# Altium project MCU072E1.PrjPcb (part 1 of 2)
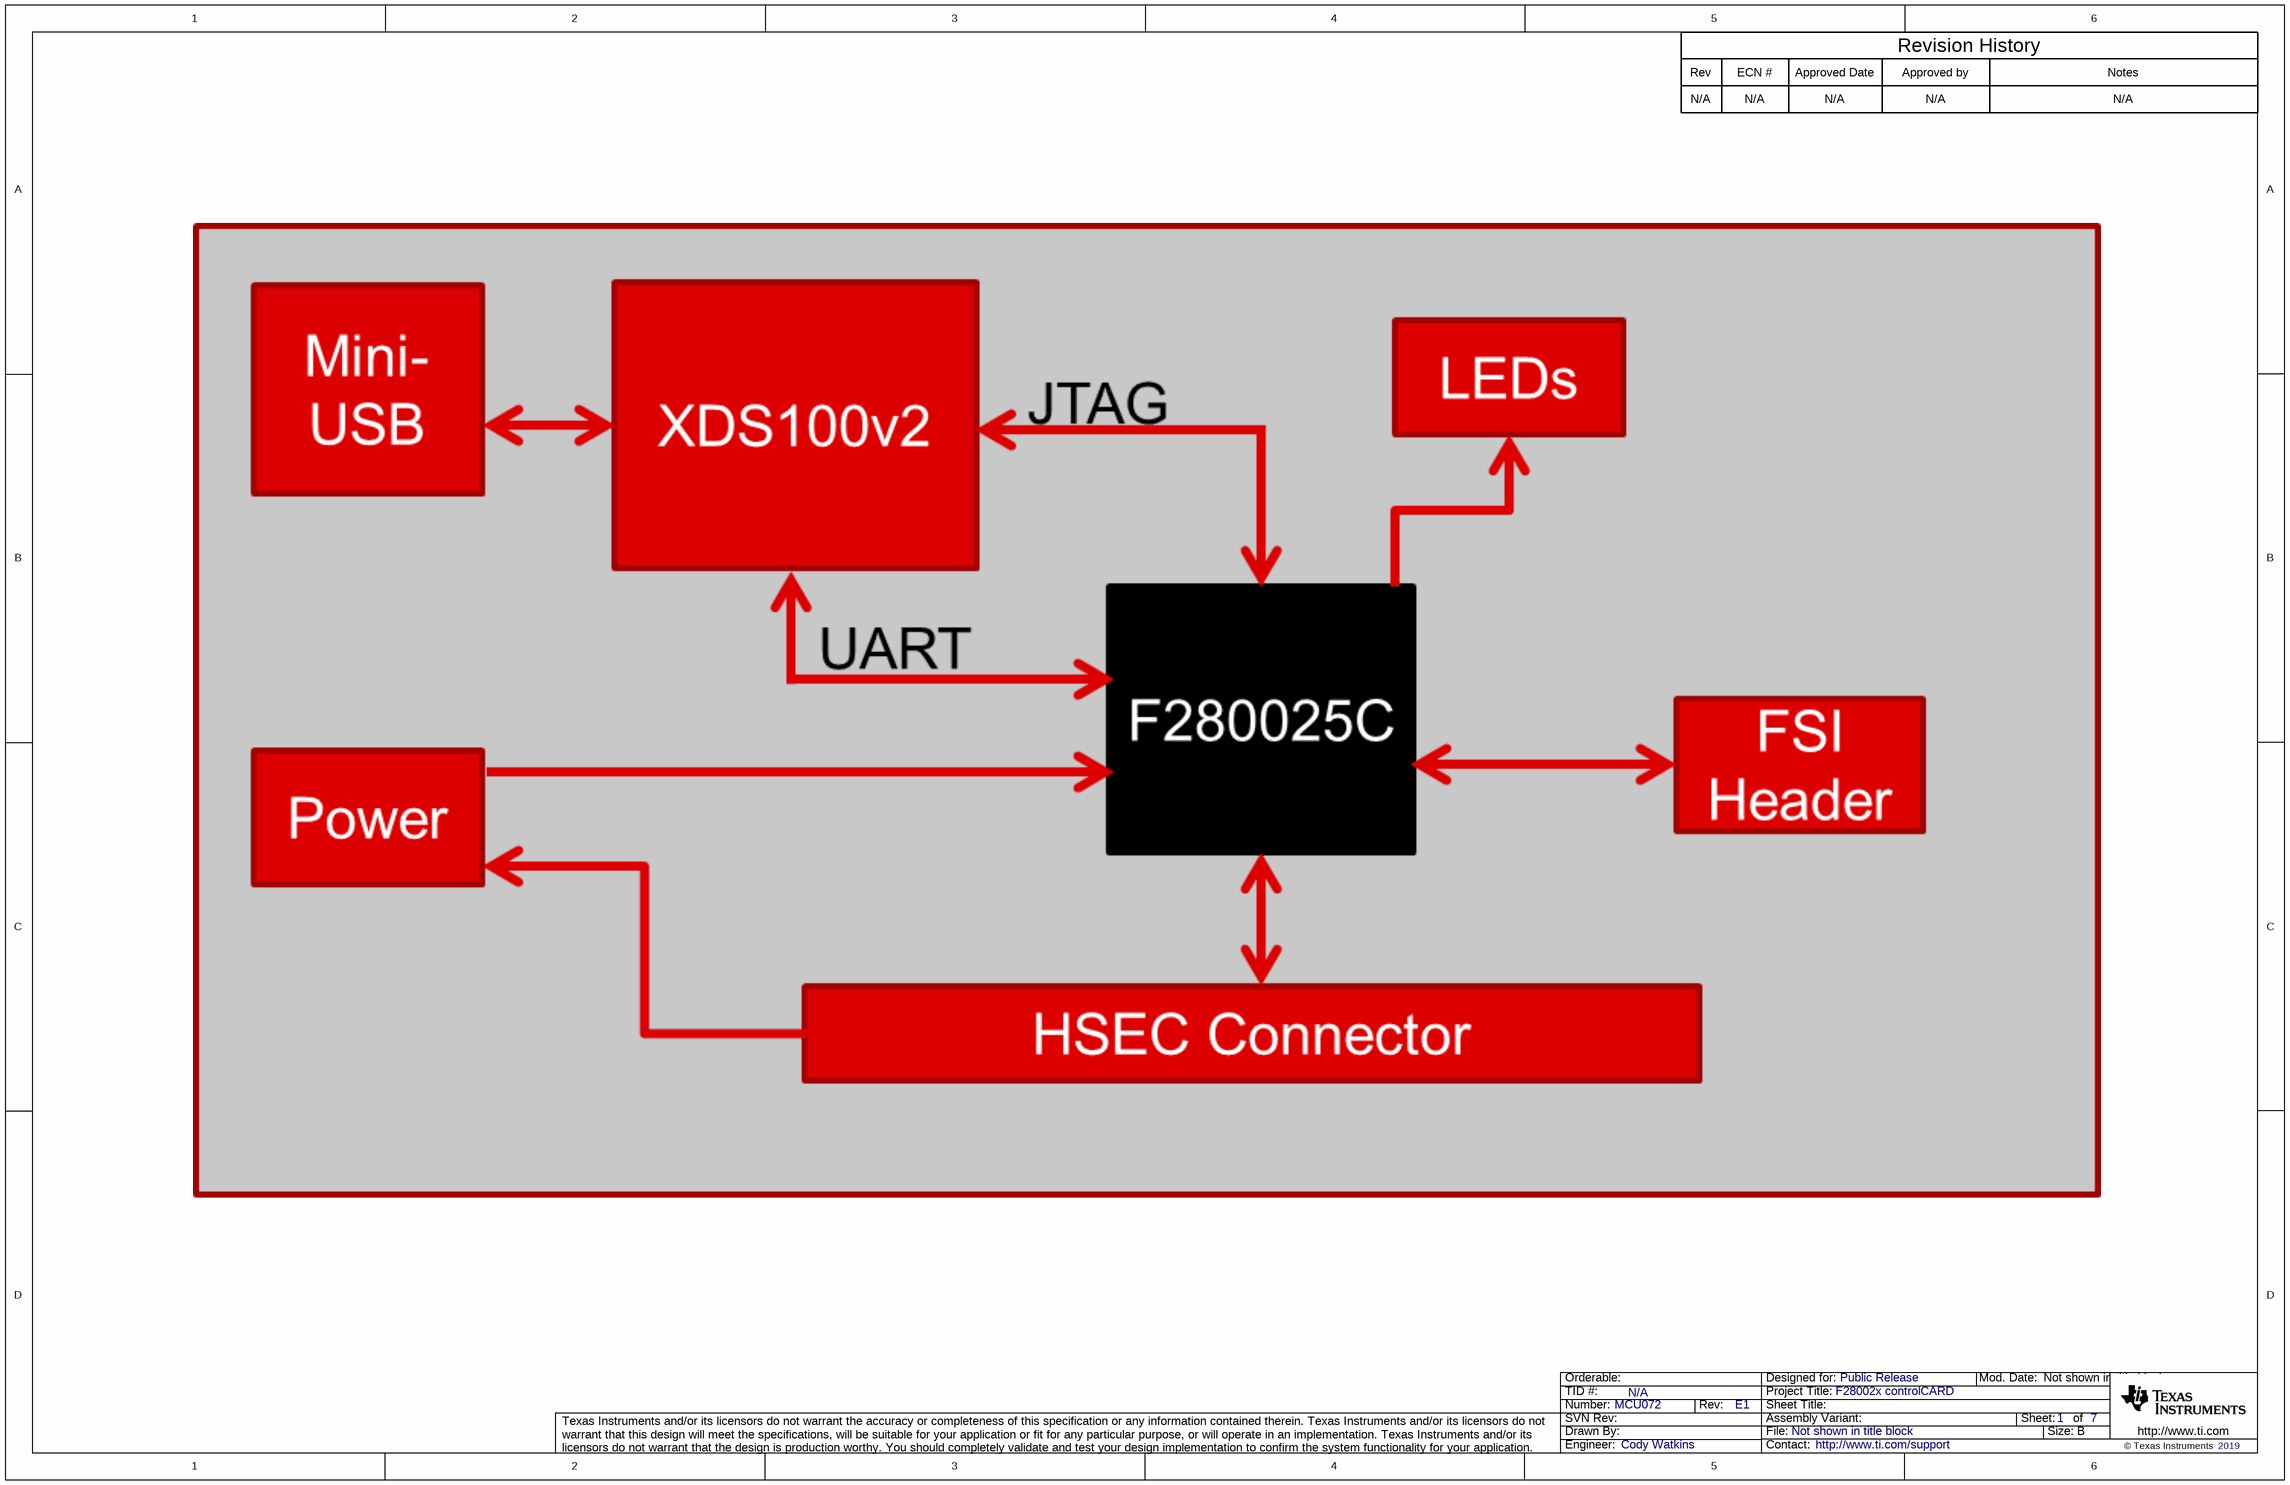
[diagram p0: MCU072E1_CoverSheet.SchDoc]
CopyrightYear: 2019; PCB_Layout: Cody Watkins; PCB_Rev: E1; PRJ_Customer: Public Release; PRJ_Engineer: Cody Watkins; PRJ_Number: MCU072; PRJ_Title: F28002x controlCARD; SCH_Rev: E1; TechSupport: http://www.ti.com/support; TID: N/A
7 sheets, 187 parts. Net scope: global (net labels, ports and power ports of the same name join across sheets).
Board file: MCU072E1_PCB.PcbDoc
Sheets:
  MCU072E1_CoverSheet.SchDoc
  MCU072E1_GPIO.SchDoc
  MCU072E1_Power.SchDoc
  MCU072E1_ADC.SchDoc
  MCU072E1_Emulator_Hardware.SchDoc
  MCU072E1_Emulator_Interface.SchDoc
  MCU072E1_Hardware.SchDoc

## Sheet MCU072E1_CoverSheet.SchDoc
size 431 x 279 mm; Date: Not shown in title block; ApprovedBy: Not shown in title block; CheckedBy: Not shown in title block; Author: Not shown in title block; CompanyName: Not shown in title block; Engineer: Not shown in title block; Organization: Not shown in title block; Address1: Not shown in title block; Address2: Not shown in title block; Address3: Not shown in title block; Address4: Not shown in title block; DocumentNumber: 1; Revision: Use project parameter SCH_Rev; SheetNumber: 1; SheetTotal: 7; PageSetup: Record=PageOptions¦CenterHorizontal=True¦CenterVertical=True¦PrintScale=1.00¦XCorrection=1.00¦YCorrection=1.00¦PrintKind=0¦BorderSize=5000000¦LeftOffset=0¦BottomOffset=0¦Orientation=2¦PaperLength=1000¦PaperWidth=1000¦Scale=100¦PaperSource=15¦PrintQuality=600¦MediaType=1¦DitherType=10¦PaperKind=Letter¦PrintScaleMode=1

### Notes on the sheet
- Rev
- N/A
- ECN #
- Approved Date
- Approved by
- Revision History
- Notes

## Sheet MCU072E1_GPIO.SchDoc
size 431 x 279 mm; Date: Not shown in title block; ApprovedBy: Not shown in title block; CheckedBy: Not shown in title block; Author: Not shown in title block; CompanyName: Not shown in title block; DrawnBy: Cody Watkins; Engineer: Not shown in title block; Organization: Not shown in title block; Address1: Not shown in title block; Address2: Not shown in title block; Address3: Not shown in title block; Address4: Not shown in title block; DocumentNumber: 2; Revision: Use project parameter SCH_Rev; SheetNumber: 2; SheetTotal: 7; PageSetup: Record=PageOptions¦CenterHorizontal=True¦CenterVertical=True¦PrintScale=1.00¦XCorrection=1.00¦YCorrection=1.00¦PrintKind=0¦BorderSize=5000000¦LeftOffset=0¦BottomOffset=0¦Orientation=2¦PaperLength=1000¦PaperWidth=1000¦Scale=100¦PaperSource=15¦PrintQuality=600¦MediaType=1¦DitherType=10¦PaperKind=Letter¦PrintScaleMode=1
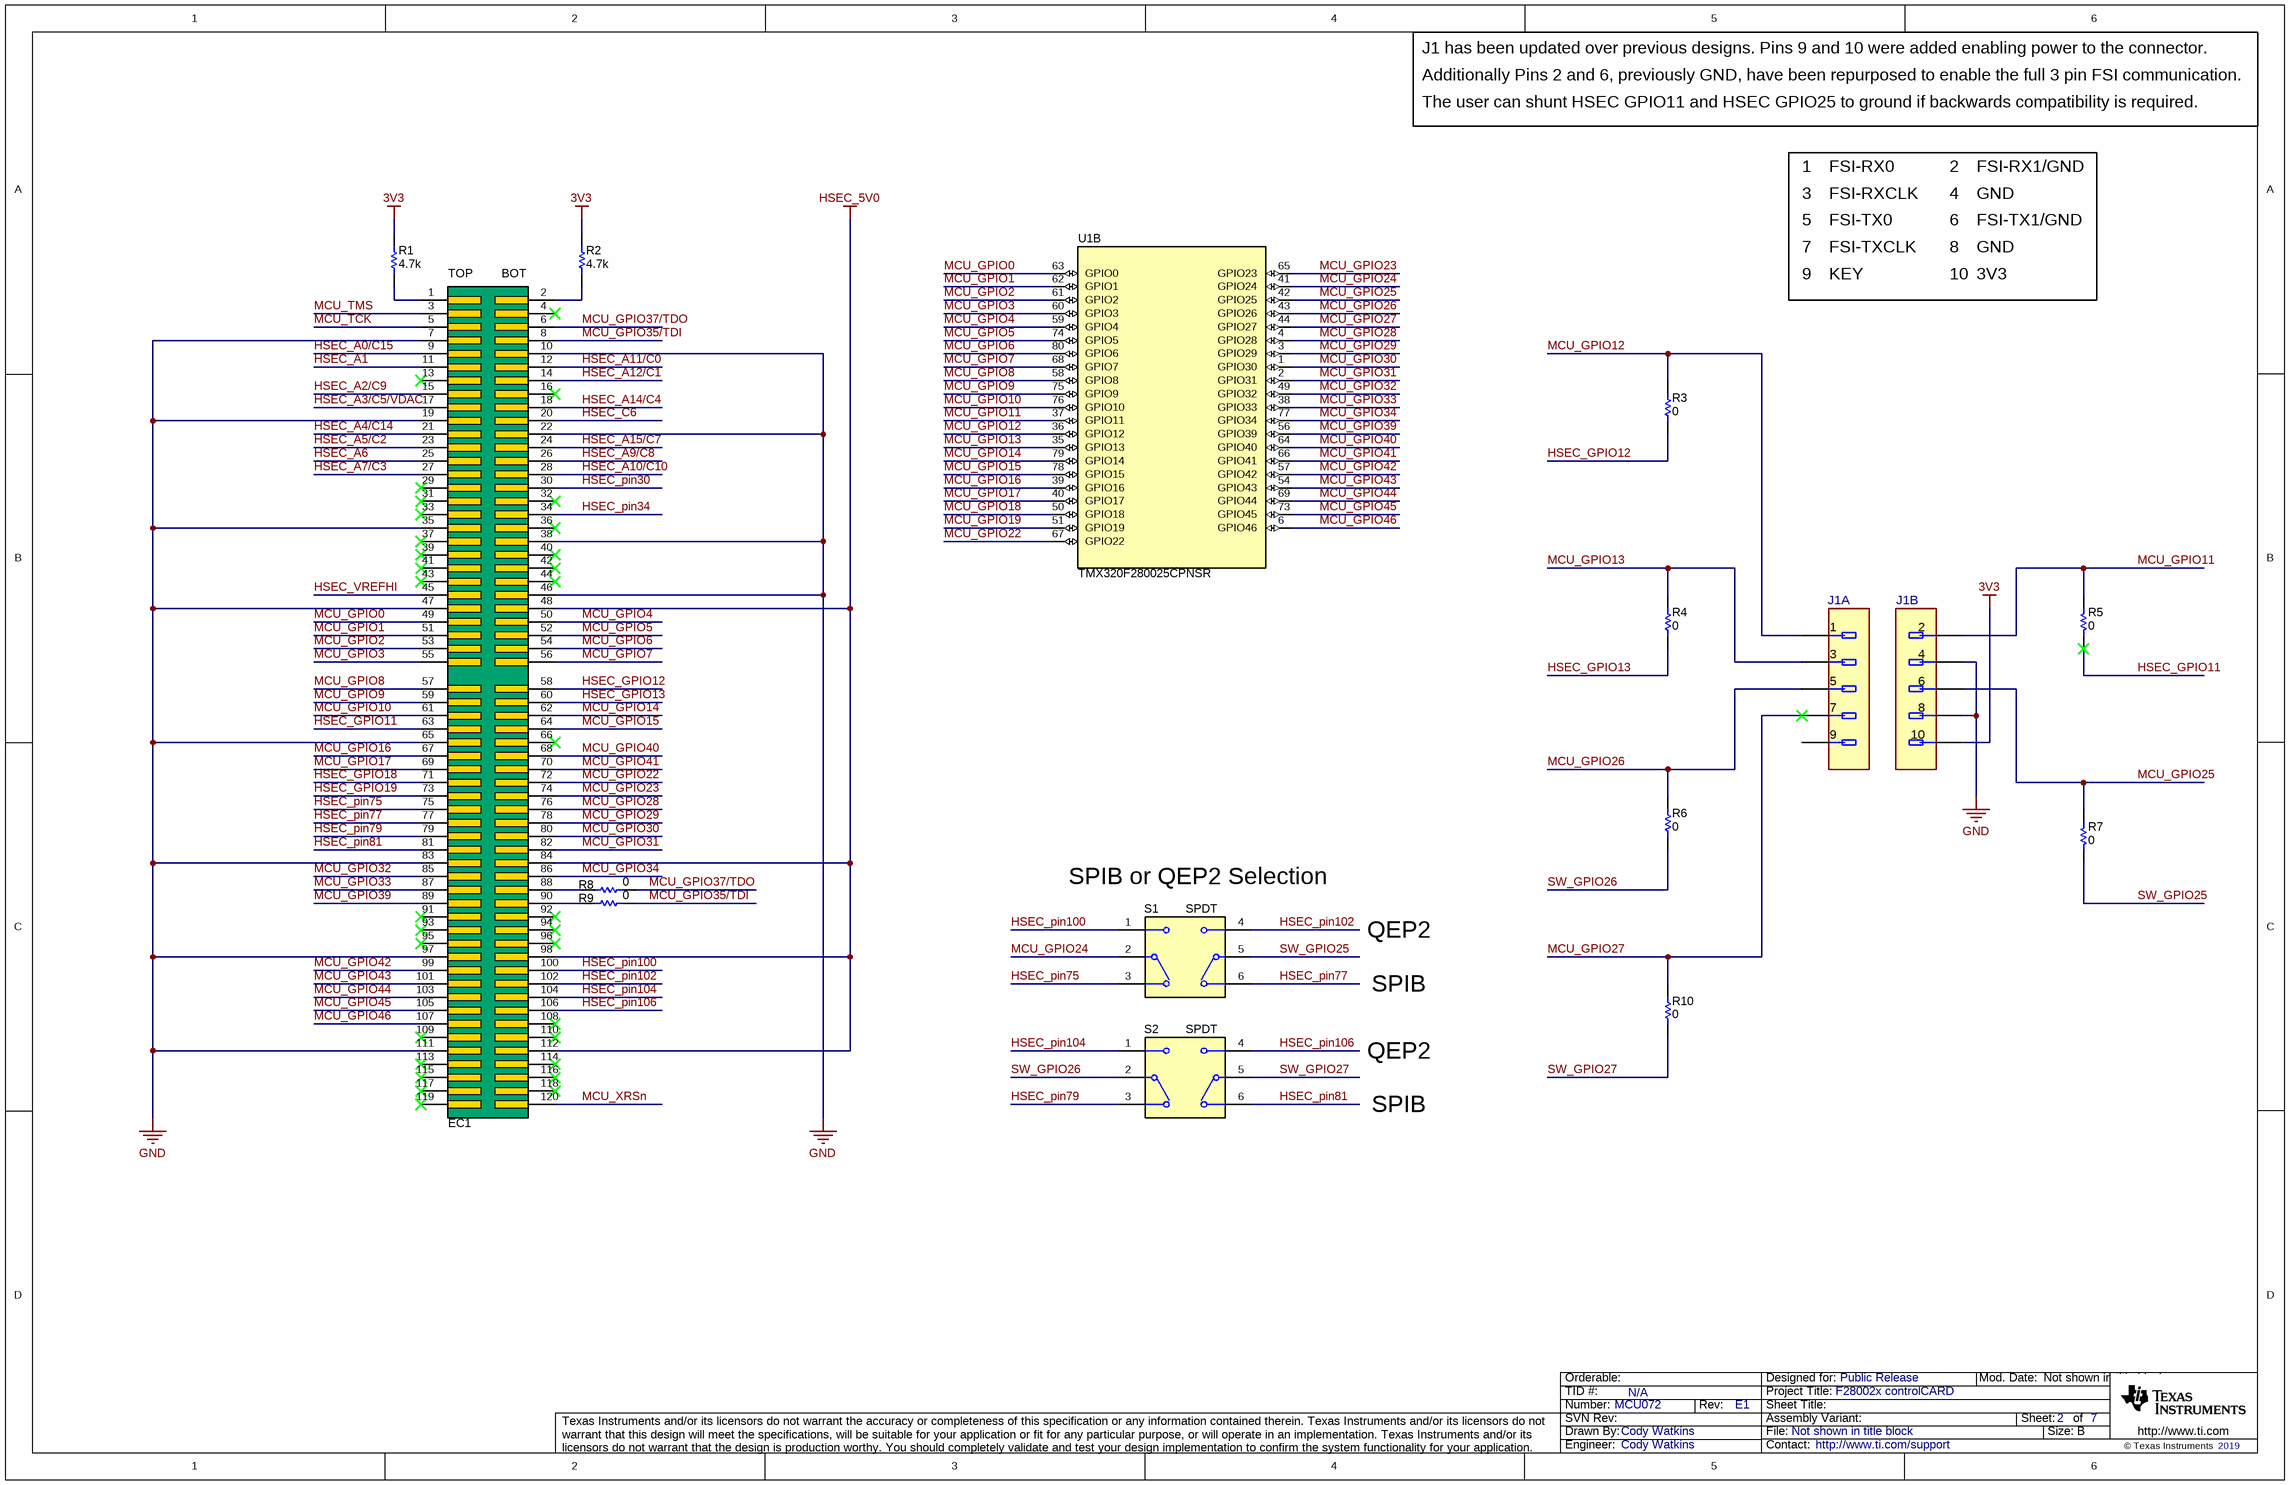
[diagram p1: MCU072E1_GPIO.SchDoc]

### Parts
EC1  controlCARD-120HSEC_Edge  [controlCARD-120HSEC_Edge]  (value not drawn)  (no BOM)
J1  TMM-105-01-T-D  [FP-TMM-105-01-T-D_HDR10-MFG]  (value not drawn)  (parts A,B of 2)
R1  ValueDisplayed: 4.7k  [0402]  (hidden comment: CRCW04024K70JNED)
R2  ValueDisplayed: 4.7k  [0402]  (hidden comment: CRCW04024K70JNED)
R3  ValueDisplayed: 0  [0603]  (hidden comment: CRCW06030000Z0EA)
R4  ValueDisplayed: 0  [0603]  (hidden comment: CRCW06030000Z0EA)
R5  ValueDisplayed: 0  [0603]  (hidden comment: CRCW06030000Z0EA)
R6  ValueDisplayed: 0  [0603]  (hidden comment: CRCW06030000Z0EA)
R7  ValueDisplayed: 0  [0603]  (hidden comment: CRCW06030000Z0EA)
R8  ValueDisplayed: 0  [0603]  (hidden comment: CRCW06030000Z0EA)
R9  ValueDisplayed: 0  [0603]  (hidden comment: CRCW06030000Z0EA)
R10  ValueDisplayed: 0  [0603]  (hidden comment: CRCW06030000Z0EA)
S1  Circuit: SPDT  [SW_CAS-D20TA]  (hidden comment: CAS-D20TA)
S2  Circuit: SPDT  [SW_CAS-D20TA]  (hidden comment: CAS-D20TA)
U1  TMX320F280025CPNSR  [PN0080A_N]  (part B of 4)

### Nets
3V3: J1.10 R1.1 R2.2
GND: EC1.7 EC1.10 EC1.19 EC1.22 EC1.35 EC1.38 EC1.46 EC1.47 EC1.65 EC1.83 EC1.97 EC1.111 J1.4 J1.8
HSEC_5V0: EC1.48 EC1.84 EC1.98 EC1.112
HSEC_A0/C15: EC1.9
HSEC_A1: EC1.11
HSEC_A2/C9: EC1.15
HSEC_A3/C5/VDAC: EC1.17
HSEC_A4/C14: EC1.21
HSEC_A5/C2: EC1.23
HSEC_A6: EC1.25
HSEC_A7/C3: EC1.27
HSEC_A9/C8: EC1.26
HSEC_A10/C10: EC1.28
HSEC_A11/C0: EC1.12
HSEC_A12/C1: EC1.14
HSEC_A14/C4: EC1.18
HSEC_A15/C7: EC1.24
HSEC_C6: EC1.20
HSEC_GPIO11: EC1.63 R5.1
HSEC_GPIO12: EC1.58 R3.1
HSEC_GPIO13: EC1.60 R4.1
HSEC_GPIO18: EC1.71
HSEC_GPIO19: EC1.73
HSEC_pin30: EC1.30
HSEC_pin34: EC1.34
HSEC_pin75: EC1.75 S1.3
HSEC_pin77: EC1.77 S1.6
HSEC_pin79: EC1.79 S2.3
HSEC_pin81: EC1.81 S2.6
HSEC_pin100: EC1.100 S1.1
HSEC_pin102: EC1.102 S1.4
HSEC_pin104: EC1.104 S2.1
HSEC_pin106: EC1.106 S2.4
HSEC_VREFHI: EC1.45
MCU_GPIO0: EC1.49 U1.63(GPIO0)
MCU_GPIO1: EC1.51 U1.62(GPIO1)
MCU_GPIO2: EC1.53 U1.61(GPIO2)
MCU_GPIO3: EC1.55 U1.60(GPIO3)
MCU_GPIO4: EC1.50 U1.59(GPIO4)
MCU_GPIO5: EC1.52 U1.74(GPIO5)
MCU_GPIO6: EC1.54 U1.80(GPIO6)
MCU_GPIO7: EC1.56 U1.68(GPIO7)
MCU_GPIO8: EC1.57 U1.58(GPIO8)
MCU_GPIO9: EC1.59 U1.75(GPIO9)
MCU_GPIO10: EC1.61 U1.76(GPIO10)
MCU_GPIO11: J1.2 R5.2 U1.37(GPIO11)
MCU_GPIO12: J1.1 R3.2 U1.36(GPIO12)
MCU_GPIO13: J1.3 R4.2 U1.35(GPIO13)
MCU_GPIO14: EC1.62 U1.79(GPIO14)
MCU_GPIO15: EC1.64 U1.78(GPIO15)
MCU_GPIO16: EC1.67 U1.39(GPIO16)
MCU_GPIO17: EC1.69 U1.40(GPIO17)
MCU_GPIO18: U1.50(GPIO18)
MCU_GPIO19: U1.51(GPIO19)
MCU_GPIO22: EC1.72 U1.67(GPIO22)
MCU_GPIO23: EC1.74 U1.65(GPIO23)
MCU_GPIO24: S1.2(C) U1.41(GPIO24)
MCU_GPIO25: J1.6 R7.2 U1.42(GPIO25)
MCU_GPIO26: J1.5 R6.2 U1.43(GPIO26)
MCU_GPIO27: J1.7 R10.2 U1.44(GPIO27)
MCU_GPIO28: EC1.76 U1.4(GPIO28)
MCU_GPIO29: EC1.78 U1.3(GPIO29)
MCU_GPIO30: EC1.80 U1.1(GPIO30)
MCU_GPIO31: EC1.82 U1.2(GPIO31)
MCU_GPIO32: EC1.85 U1.49(GPIO32)
MCU_GPIO33: EC1.87 U1.38(GPIO33)
MCU_GPIO34: EC1.86 U1.77(GPIO34)
MCU_GPIO35/TDI: EC1.8 R9.1
MCU_GPIO37/TDO: EC1.6 R8.1
MCU_GPIO39: EC1.89 U1.56(GPIO39)
MCU_GPIO40: EC1.68 U1.64(GPIO40)
MCU_GPIO41: EC1.70 U1.66(GPIO41)
MCU_GPIO42: EC1.99 U1.57(GPIO42)
MCU_GPIO43: EC1.101 U1.54(GPIO43)
MCU_GPIO44: EC1.103 U1.69(GPIO44)
MCU_GPIO45: EC1.105 U1.73(GPIO45)
MCU_GPIO46: EC1.107 U1.6(GPIO46)
MCU_TCK: EC1.5
MCU_TMS: EC1.3
MCU_XRSn: EC1.120
SW_GPIO25: R7.1 S1.5(C)
SW_GPIO26: R6.1 S2.2(C)
SW_GPIO27: R10.1 S2.5(C)
NetEC1_1: EC1.1 R1.2
NetEC1_2: EC1.2 R2.1
NetEC1_88: EC1.88 R8.2
NetEC1_90: EC1.90 R9.2

Not connected (* = marked no-connect by the designer): EC1 4* 13* 16* 29* 31* 32* 33* 36* 37* 39* 40* 41* 42* 43* 44* 66* 91* 92* 93* 94* 95* 96* 108* 109* 110* 113* 114* 115* 116* 117* 118* 119*; J1 9

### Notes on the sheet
- J1 has been updated over previous designs. Pins 9 and 10 were added enabling power to the connector.
- Additionally Pins 2 and 6, previously GND, have been repurposed to enable the full 3 pin FSI communication.
- The user can shunt HSEC GPIO11 and HSEC GPIO25 to ground if backwards compatibility is required.
- 1
- FSI-RX0
- 2
- FSI-RX1/GND
- 3
- 5
- FSI-RXCLK
- FSI-TX0
- 4
- 6
- FSI-TX1/GND
- GND
- 7
- 9
- FSI-TXCLK
- KEY
- 8
- 10
- 3V3
- (near S1) SPIB or QEP2 Selection
- QEP2
- SPIB

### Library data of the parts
EC1 = CMP-0003813-2: C2000 controlCARD-120HSEC Edge Connector for Samtec HSEC8-160-01-L-DV-A-BL; Manufacturer: Any; Note: The pin numbering does not match Samtec datasheet
J1 = CMP-0086568-1: Board-To-Board Connector, TMM Series, 10 Contacts, Header, 2 mm, Through Hole, 2 Rows; Manufacturer: Samtec; ContactFinish: Tin,Nickel; Voltage_V: 281V; Symbol Name: SYM-TMM-105-01-T-D; Row_Count: 2; Current_A: 3.2A
R1 R2 = CMP-0026938-5: RES, 4.7 k, 5%, 0.063 W, AEC-Q200 Grade 0, 0402; Manufacturer: Vishay-Dale; Value: 4.7k; Value_Code: 4k70; Power_W: 63mW; Value2: 0.063W; VDC_V: 50V; TempCo: 200 ppm/C; EIA_Code: E24; AEC Category: Q200; AEC Qualified: Y; AEC Grade: 0; SizeArea_mm2: 0.5; SizeX_mm: 1; SizeZ_mm: 0.6
R3-R10 = CMP-0025697-4: RES, 0, 5%, 0.1 W, AEC-Q200 Grade 0, 0603; Manufacturer: Vishay-Dale; Value: 0; Value_Code: 0000; Power_W: 100mW; Value2: 0.1W; VDC_V: 75V; TempCo: 200 ppm/C; EIA_Code: E24; AEC Category: Q200; AEC Qualified: Y; SizeArea_mm2: 1.28; SizeX_mm: 1.6; SizeY_mm: 0.8; SizeZ_mm: 1
S1 S2 = CMP-0002233-1: Switch, Dual SPDT,  2 Pos, 0.1A, 6VDC, SMD; Manufacturer: Copal Electronics; VDC_V: 6V; SwitchFunction: On-On; PositionCount: 2; CurrentRating_mA: 100A
U1 = CMP-0750188-2: TMX320F280025CPNSR, PN0080A (LQFP-80); Alternate Manufacturer: Texas Instruments; SizeY_mm: 14; CompType: IC; AEC Category: Q200; AEC Qualified: N; SizeAreaWB_mm2: 256; SizeArea_mm2: 196; SizeZ_mm: 1.6

## Sheet MCU072E1_Power.SchDoc
size 431 x 279 mm; Date: Not shown in title block; ApprovedBy: Not shown in title block; CheckedBy: Not shown in title block; Author: Not shown in title block; CompanyName: Not shown in title block; DrawnBy: Cody Watkins; Engineer: Not shown in title block; Organization: Not shown in title block; Address1: Not shown in title block; Address2: Not shown in title block; Address3: Not shown in title block; Address4: Not shown in title block; DocumentNumber: 3; Revision: Use project parameter SCH_Rev; SheetNumber: 3; SheetTotal: 7; PageSetup: Record=PageOptions¦CenterHorizontal=True¦CenterVertical=True¦PrintScale=1.00¦XCorrection=1.00¦YCorrection=1.00¦PrintKind=0¦BorderSize=5000000¦LeftOffset=0¦BottomOffset=0¦Orientation=2¦PaperLength=1000¦PaperWidth=1000¦Scale=100¦PaperSource=15¦PrintQuality=600¦MediaType=1¦DitherType=10¦PaperKind=Letter¦PrintScaleMode=1
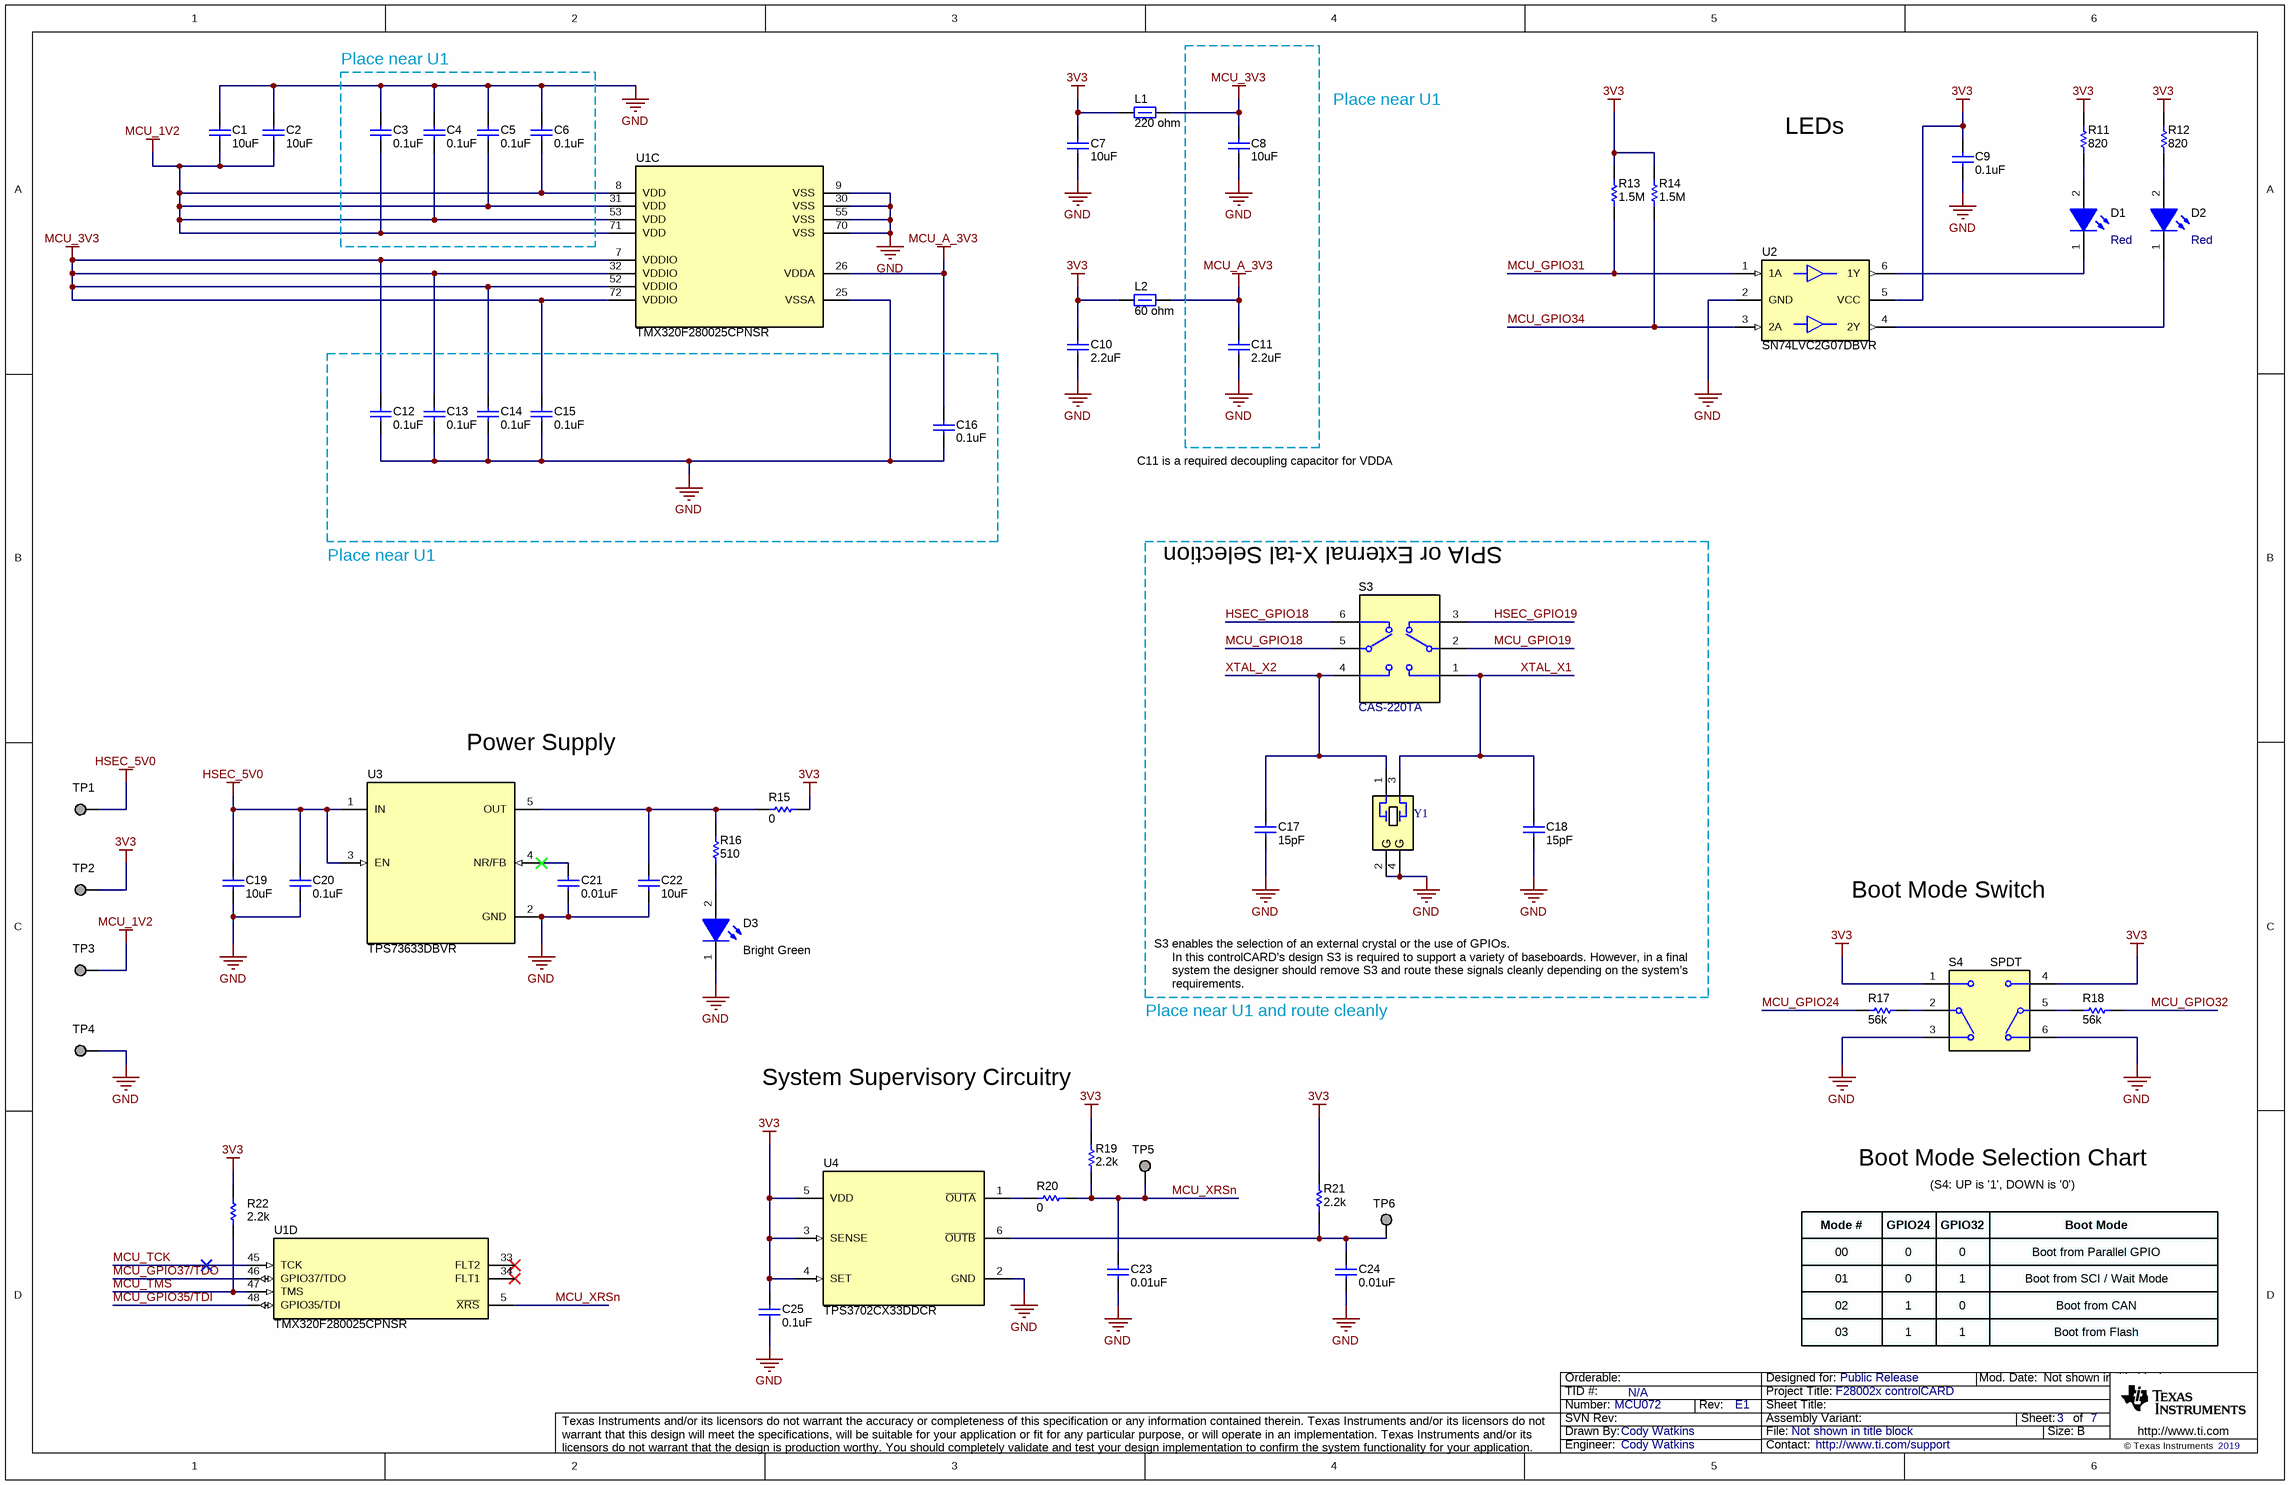
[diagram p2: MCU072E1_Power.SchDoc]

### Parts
C1  ValueDisplayed: 10uF  [0603]  (hidden comment: GRM188R61A106ME69D)
C2  ValueDisplayed: 10uF  [0603]  (hidden comment: GRM188R61A106ME69D)
C3  ValueDisplayed: 0.1uF  [0402]  (hidden comment: 885012105010)
C4  ValueDisplayed: 0.1uF  [0402]  (hidden comment: 885012105010)
C5  ValueDisplayed: 0.1uF  [0402]  (hidden comment: 885012105010)
C6  ValueDisplayed: 0.1uF  [0402]  (hidden comment: 885012105010)
C7  ValueDisplayed: 10uF  [0805_HV]  (hidden comment: LMK212ABJ106KG-T)
C8  ValueDisplayed: 10uF  [0603]  (hidden comment: GRM188R61A106ME69D)
C9  ValueDisplayed: 0.1uF  [0402]  (hidden comment: 885012105010)
C10  ValueDisplayed: 2.2uF  [0603]  (hidden comment: CGA3E3X5R1A225K080AB)
C11  ValueDisplayed: 2.2uF  [0603]  (hidden comment: CGA3E3X5R1A225K080AB)
C12  ValueDisplayed: 0.1uF  [0402]  (hidden comment: 885012105010)
C13  ValueDisplayed: 0.1uF  [0402]  (hidden comment: 885012105010)
C14  ValueDisplayed: 0.1uF  [0402]  (hidden comment: 885012105010)
C15  ValueDisplayed: 0.1uF  [0402]  (hidden comment: 885012105010)
C16  ValueDisplayed: 0.1uF  [0402]  (hidden comment: 885012105010)
C17  ValueDisplayed: 15pF  [0402]  (hidden comment: 885012005056)
C18  ValueDisplayed: 15pF  [0402]  (hidden comment: 885012005056)
C19  ValueDisplayed: 10uF  [0603]  (hidden comment: GRM188R61A106ME69D)
C20  ValueDisplayed: 0.1uF  [0402]  (hidden comment: 885012105010)
C21  ValueDisplayed: 0.01uF  [0402]  (hidden comment: 0402ZC103KAT2A)
C22  ValueDisplayed: 10uF  [0603]  (hidden comment: GRM188R61A106ME69D)
C23  ValueDisplayed: 0.01uF  [0402]  (hidden comment: 0402ZC103KAT2A)
C24  ValueDisplayed: 0.01uF  [0402]  (hidden comment: 0402ZC103KAT2A)
C25  ValueDisplayed: 0.1uF  [0402]  (hidden comment: 885012105010)
D1  value Red  [WL-SMCW_RED_0805]  (hidden comment: 150080SS75000)
D2  value Red  [WL-SMCW_RED_0805]  (hidden comment: 150080SS75000)
D3  value Bright Green  [WL-SMCW_Green_0805]  (hidden comment: 150080VS75000)
L1  value 220 ohm  [0805_HV]  (hidden comment: BLM21PG221SN1D)
L2  value 60 ohm  [0805_HV]  (hidden comment: BKP2125HS600-T)
R11  ValueDisplayed: 820  [0402]  (hidden comment: CRCW0402820RJNED)
R12  ValueDisplayed: 820  [0402]  (hidden comment: CRCW0402820RJNED)
R13  ValueDisplayed: 1.5M  [0402]  (hidden comment: CRCW04021M50JNED)
R14  ValueDisplayed: 1.5M  [0402]  (hidden comment: CRCW04021M50JNED)
R15  ValueDisplayed: 0  [0805_HV]  (hidden comment: CRCW08050000Z0EA)
R16  ValueDisplayed: 510  [0402]  (hidden comment: CRCW0402510RJNED)
R17  ValueDisplayed: 56k  [0402]  (hidden comment: CRCW040256K0JNED)
R18  ValueDisplayed: 56k  [0402]  (hidden comment: CRCW040256K0JNED)
R19  ValueDisplayed: 2.2k  [0402]  (hidden comment: CRCW04022K20JNED)
R20  ValueDisplayed: 0  [0402]  (hidden comment: CRCW04020000Z0ED)
R21  ValueDisplayed: 2.2k  [0402]  (hidden comment: CRCW04022K20JNED)
R22  ValueDisplayed: 2.2k  [0402]  (hidden comment: CRCW04022K20JNED)
S3  CAS-220TA  [SW_CAS-220TA]
S4  Circuit: SPDT  [SW_CAS-D20TA]  (hidden comment: CAS-D20TA)
TP1  TESTPOINT  [TP_50MIL-25MILHOLE]  (value not drawn)  (no BOM)
TP2  TESTPOINT  [TP_50MIL-25MILHOLE]  (value not drawn)  (no BOM)
TP3  TESTPOINT  [TP_50MIL-25MILHOLE]  (value not drawn)  (no BOM)
TP4  TESTPOINT  [TP_50MIL-25MILHOLE]  (value not drawn)  (no BOM)
TP5  TESTPOINT  [TP_50MIL-25MILHOLE]  (value not drawn)  (no BOM)
TP6  TESTPOINT  [TP_50MIL-25MILHOLE]  (value not drawn)  (no BOM)
U1  TMX320F280025CPNSR  [PN0080A_N]  (parts C,D of 4)
U2  SN74LVC2G07DBVR  [DBV0006A_N]
U3  TPS73633DBVR  [DBV0005A_N]
U4  TPS3702CX33DDCR  [DDC0006A_N]
Y1  ECS-200-18-30B-AGN-TR  [ECS_ECX-53B]  (value not drawn)

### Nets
3V3: C7.2 C9.1 C10.2 C25.1 L1.1 L2.1 R11.2 R12.2 R13.2 R14.2 R15.2 R19.2 R21.2 R22.2 S4.1 S4.4 TP2.1 U2.5(VCC) U4.3(SENSE) U4.4(SET) U4.5(VDD)
GND: C1.2 C2.2 C3.1 C4.1 C5.1 C6.1 C7.1 C8.2 C9.2 C10.1 C11.1 C12.2 C13.2 C14.2 C15.2 C16.2 C17.2 C18.2 C19.2 C20.2 C21.1 C22.1 C23.1 C24.1 C25.2 D3.1(K) S4.3 S4.6 TP4.1 U1.9(VSS) U1.25(VSSA) U1.30(VSS) U1.55(VSS) U1.70(VSS) U2.2(GND) U3.2(GND) U4.2(GND) Y1.2(GND) Y1.4(GND)
HSEC_5V0: C19.1 C20.1 TP1.1 U3.1(IN) U3.3(EN)
MCU_1V2: C1.1 C2.1 C3.2 C4.2 C5.2 C6.2 TP3.1 U1.8(VDD) U1.31(VDD) U1.53(VDD) U1.71(VDD)
MCU_3V3: C8.1 C12.1 C13.1 C14.1 C15.1 L1.2 U1.7(VDDIO) U1.32(VDDIO) U1.52(VDDIO) U1.72(VDDIO)
MCU_A_3V3: C11.2 C16.1 L2.2 U1.26(VDDA)
HSEC_GPIO18: S3.6
HSEC_GPIO19: S3.3
MCU_GPIO18: S3.5
MCU_GPIO19: S3.2
MCU_GPIO24: R17.2
MCU_GPIO31: R13.1 U2.1(1A)
MCU_GPIO32: R18.1
MCU_GPIO34: R14.1 U2.3(2A)
MCU_GPIO35/TDI: U1.48(GPIO35/TDI)
MCU_GPIO37/TDO: U1.46(GPIO37/TDO)
MCU_TCK: U1.45(TCK)
MCU_TMS: R22.1 U1.47(TMS)
MCU_XRSn: C23.2 R19.1 R20.2 TP5.1 U1.5(~{XRS})
XTAL_X1: C18.1 S3.1 Y1.3
XTAL_X2: C17.1 S3.4 Y1.1
NetC21_2: C21.2 U3.4(NR/FB)
NetC22_2: C22.2 R15.1 R16.2 U3.5(OUT)
NetC24_2: C24.2 R21.1 TP6.1 U4.6(~{OUTB})
NetD1_1: D1.1(K) U2.6(1Y)
NetD1_2: D1.2(A) R11.1
NetD2_1: D2.1(K) U2.4(2Y)
NetD2_2: D2.2(A) R12.1
NetD3_2: D3.2(A) R16.1
NetR17_1: R17.1 S4.2(C)
NetR18_2: R18.2 S4.5(C)
NetR20_1: R20.1 U4.1(~{OUTA})

Not connected (* = marked no-connect by the designer): U1 33(FLT2)* 34(FLT1)*

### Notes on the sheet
- Place near U1
- LEDs
- C11 is a required decoupling capacitor for VDDA
- SPIA or External X-tal Selection
- Power Supply
- Boot Mode Switch
- In this controlCARD’s design S3 is required to support a variety of baseboards. However, in a final
- system the designer should remove S3 and route these signals cleanly depending on the system’s
- S3 enables the selection of an external crystal or the use of GPIOs.
- Place near U1 and route cleanly
- requirements.
- System Supervisory Circuitry
- Boot Mode Selection Chart
- Mode #
- GPIO24
- GPIO32
- (S4: UP is '1', DOWN is '0')
- Boot Mode
- 00
- 01
- 02
- 0
- 1
- Boot from Parallel GPIO
- Boot from SCI / Wait Mode
- Boot from CAN
- 03
- Boot from Flash

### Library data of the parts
C1 C2 C8 C19 C22 = CMP-0007318-5: CAP, CERM, 10 uF, 10 V, +/- 20%, X5R, 0603; Manufacturer: MuRata; Polarized: N; Value: 10uF; U/M: EA; Cap_F: 10µF; Value1: Unknown; VDC_V: 10V; TaMin_C: -55°C; TaMax_C: 85°C; AEC Category: Q200; SizeArea_mm2: 1.28; SizeAreaWB_mm2: 4.68; SizeX_mm: 1.6; SizeY_mm: 0.8; SizeZ_mm: 1
C3-C6 C12-C16 = CMP-0006221-2: CAP, CERM, 0.1 uF, 10 V, +/- 20%, X5R, 0402; Manufacturer: Wurth Elektronik; Polarized: N; Value: 0.1uF; U/M: EA; Cap_F: 100nF; Value1: Unknown; VDC_V: 10V; TaMin_C: -55°C; TaMax_C: 85°C; SizeArea_mm2: 0.5; SizeAreaWB_mm2: 3; SizeX_mm: 1; SizeZ_mm: 0.6; AEC Category: Q200
C7 = CMP-0008395-2: CAP, CERM, 10 uF, 10 V, +/- 10%, X5R, 0805; Manufacturer: Taiyo Yuden; Polarized: N; Value: 10uF; U/M: EA; Cap_F: 10µF; Value1: Unknown; VDC_V: 10V; TaMin_C: -55°C; TaMax_C: 85°C; Cap_Case: 0805; AEC Category: Q200; SizeArea_mm2: 2.5; SizeAreaWB_mm2: 6.75; SizeX_mm: 2; SizeY_mm: 1.25; SizeZ_mm: 1.45
C9 C20 C25 = CMP-0006221-2: CAP, CERM, 0.1 uF, 10 V, +/- 20%, X5R, 0402; Manufacturer: Wurth Elektronik; Polarized: N; Value: 0.1uF; U/M: EA; Cap_F: 100nF; Value1: Unknown; VDC_V: 10V; TaMin_C: -55°C; TaMax_C: 85°C; AEC Category: Q200; SizeArea_mm2: 0.5; SizeAreaWB_mm2: 3; SizeX_mm: 1; SizeZ_mm: 0.6
C10 C11 = CMP-0007091-5: CAP, CERM, 2.2 uF, 10 V, +/- 10%, X5R, AEC-Q200 Grade 3, 0603; Manufacturer: TDK; Polarized: N; Value: 2.2uF; U/M: EA; Cap_F: 2.2µF; Value1: Unknown; VDC_V: 10V; TaMin_C: -55°C; TaMax_C: 85°C; AEC Category: Q200; AEC Qualified: Y; AEC Grade: 3; SizeArea_mm2: 1.28; SizeAreaWB_mm2: 4.68; SizeX_mm: 1.6; SizeY_mm: 0.8; SizeZ_mm: 1
C17 C18 = CMP-0006216-2: CAP, CERM, 15 pF, 50 V, +/- 5%, C0G/NP0, 0402; Manufacturer: Wurth Elektronik; Polarized: N; Value: 15pF; U/M: EA; Value1: Unknown; VDC_V: 50V; TaMin_C: -55°C; TaMax_C: 125°C; AEC Category: Q200; SizeArea_mm2: 0.5; SizeAreaWB_mm2: 3; SizeX_mm: 1; SizeZ_mm: 0.6
C21 C23 C24 = CMP-0006203-2: CAP, CERM, 0.01 uF, 10 V, +/- 10%, X7R, 0402; Manufacturer: AVX; Polarized: N; Value: 0.01uF; U/M: EA; Cap_F: 10nF; Value1: Unknown; VDC_V: 10V; TaMin_C: -55°C; TaMax_C: 125°C; AEC Category: Q200; SizeArea_mm2: 0.5; SizeAreaWB_mm2: 3; SizeX_mm: 1; SizeZ_mm: 0.6
D1 D2 = CMP-0002951-3: LED, Red, SMD; Manufacturer: Wurth Elektronik; Type: AlInGaP; Vf_V: 1.9V; Io_A: 30mA; Vr_V: 5V; Ir_A: 25µA; Tjmax_C: 85°C; Power_TotalModule: 72mW; Value1: 0.072W; Angle: 140
D3 = CMP-0002960-2: LED, Bright Green, SMD; Manufacturer: Wurth Elektronik; Type: AlInGaP; Vf_V: 2V; Io_A: 20mA; Vr_V: 5V; Tjmax_C: 85°C; Power_TotalModule: 72mW; Value1: 0.072W; Angle: 140; U/M: EA
L1 = CMP-0003363-1: Ferrite Bead, 220 ohm @ 100 MHz, 2 A, 0805; Manufacturer: MuRata; Imax_A: 2A; DCR_ohm: 0.045; Value1: 0.045 ohm; ZTyp@100MHz_Ohm: 220; SizeArea_mm2: 2.5; SizeAreaWB_mm2: 6.75; SizeX_mm: 2; SizeY_mm: 1.25; SizeZ_mm: 1.45
L2 = CMP-0003306-1: Ferrite Bead, 60 ohm @ 100 MHz, 3 A, 0805; Manufacturer: Taiyo Yuden; Imax_A: 3A; DCR_ohm: 0.025; Value1: 0.025 ohm; ZTyp@100MHz_Ohm: 60; SizeArea_mm2: 2.5; SizeAreaWB_mm2: 6.75; SizeX_mm: 2; SizeY_mm: 1.25; SizeZ_mm: 1.45
R11 R12 = CMP-0026979-3: RES, 820, 5%, 0.063 W, AEC-Q200 Grade 0, 0402; Manufacturer: Vishay-Dale; Power_W: 63mW; TempCo: 200 ppm/C; Value_Code: 820R; Value: 820; EIA_Code: E24; SizeX_mm: 1; SizeY_mm: 0.5; SizeZ_mm: 0.6; Value2: 0.063W; AEC Qualified: Y; VDC_V: 50V; AEC Category: Q200; AEC Grade: 0
R13 R14 = CMP-0026863-2: RES, 1.5 M, 5%, 0.063 W, AEC-Q200 Grade 0, 0402; Manufacturer: Vishay-Dale; Power_W: 63mW; TempCo: 200 ppm/C; Value_Code: 1M50; Value: 1.5Meg; EIA_Code: E24; SizeX_mm: 1; SizeY_mm: 0.5; SizeZ_mm: 0.6; Value2: 0.063W; AEC Qualified: Y; VDC_V: 50V; AEC Category: Q200; AEC Grade: 0
R15 = CMP-0020442-3: RES, 0, 5%, 0.125 W, AEC-Q200 Grade 0, 0805; Manufacturer: Vishay-Dale; Value: 0; Value_Code: 0000; Power_W: 125mW; Value2: 0.125W; VDC_V: 150V; TempCo: 200 ppm/C; EIA_Code: E24; AEC Category: Q200; AEC Qualified: Y; SizeArea_mm2: 2.5; SizeX_mm: 2; SizeY_mm: 1.25; SizeZ_mm: 1.45
R16 = CMP-0026944-3: RES, 510, 5%, 0.063 W, AEC-Q200 Grade 0, 0402; Manufacturer: Vishay-Dale; Power_W: 63mW; TempCo: 200 ppm/C; Value_Code: 510R; Value: 510; EIA_Code: E24; SizeX_mm: 1; SizeY_mm: 0.5; SizeZ_mm: 0.6; Value2: 0.063W; AEC Qualified: Y; VDC_V: 50V; AEC Category: Q200; AEC Grade: 0
R17 R18 = CMP-0026949-3: RES, 56 k, 5%, 0.063 W, AEC-Q200 Grade 0, 0402; Manufacturer: Vishay-Dale; Value: 56k; Value_Code: 56k0; Power_W: 63mW; Value2: 0.063W; VDC_V: 50V; TempCo: 200 ppm/C; EIA_Code: E24; AEC Category: Q200; AEC Qualified: Y; AEC Grade: 0; SizeArea_mm2: 0.5; SizeX_mm: 1; SizeZ_mm: 0.6
R19 R21 R22 = CMP-0026890-5: RES, 2.2 k, 5%, 0.063 W, AEC-Q200 Grade 0, 0402; Manufacturer: Vishay-Dale; Value: 2.2k; Value_Code: 2k20; Power_W: 63mW; Value2: 0.063W; VDC_V: 50V; TempCo: 200 ppm/C; EIA_Code: E24; AEC Category: Q200; AEC Qualified: Y; AEC Grade: 0; SizeArea_mm2: 0.5; SizeX_mm: 1; SizeZ_mm: 0.6
R20 = CMP-0026822-3: RES, 0, 5%, 0.063 W, AEC-Q200 Grade 0, 0402; Manufacturer: Vishay-Dale; Value: 0; Value_Code: 0000; Power_W: 63mW; Value2: 0.063W; VDC_V: 50V; TempCo: 200 ppm/C; SizeArea_mm2: 0.5; SizeX_mm: 1; SizeZ_mm: 0.6; EIA_Code: E24; AEC Category: Q200; AEC Qualified: Y
S3 = CMP-0002123-2: SLIDE SWITCH DPDT  .1A, SMT; Manufacturer: Copal Electronics; CurrentRating_mA: 100A; SwitchFunction: On-On; VDC_V: 6V; PositionCount: 2
S4 = CMP-0002233-1: as S1 on sheet MCU072E1_GPIO
TP1-TP6 = CMP-0078143-2: TEST POINT.  No entry in BOM.
U1 = CMP-0750188-2: as U1 on sheet MCU072E1_GPIO
U2 = CMP-0051789-2: Dual Buffer/Driver with Open-Drain Output, DBV0006A, LARGE T&R; Manufacturer: Texas Instruments; 3-State Output: No; Bits(#): 2; F @ Nom Voltage(Max)(Mhz): 150; ICC @ Nom Voltage(Max)(mA): 0.01; Input Type: CMOS/TTL; Logic: True; Output Drive (IOL/IOH)(Max)(mA): 32/-32; Output Type: CMOS; Rating: Catalog; Sub-Family: Inverting Buffer/Driver; Technology Family: LVC; tpd @ Nom Voltage(Max)(ns): 8.6,4.4,3.7,2.9; VCC(Max)(V): 5.5; VCC(Min)(V): 1.65; Voltage(Nom)(V): 1.8,2.5,3.3,5; AEC Category: Q200; AEC Qualified: N; CompType: IC; Green_Lifecycle: Active; Green_REACh: Passed; SizeArea_mm2: 8.12; SizeAreaWB_mm2: 14.82; SizeX_mm: 2.8; SizeY_mm: 2.9; SizeZ_mm: 1.45
U3 = CMP-0036866-2: Single Output Low Noise LDO, 400 mA, Fixed 3.3 V Output, 1.7 to 5.5 V Input, with Reverse Current Protection, 5-pin SOT-23 (DBV), -40 to 85 degC, Green (RoHS & no Sb/Br); Manufacturer: Texas Instruments; Alternate PartNumber: TPS73633DBVT; Accuracy(%): 1; Fixed Output Options(V): 3.3; Iout(Max)(A): 0.4; Iq(Typ)(mA): 0.3; Rating: Catalog; SubFamily: Single Channel LDO; Vdo(Typ)(mV): 75; Vin(Max)(V): 5.5; Vin(Min)(V): 1.7; AEC Category: Q200; AEC Qualified: N; CompType: IC; Green_Lifecycle: Active; Green_REACh: Passed; SizeArea_mm2: 8.12; SizeAreaWB_mm2: 14.82; SizeX_mm: 2.8; SizeY_mm: 2.9; SizeZ_mm: 1.45
U4 = CMP-0067340-3: High-Accuracy, Fixed-Threshold OV/UV Monitor, DDC0006A (SOT-23-T-6); Alternate PartNumber: TPS3702CX33DDCT; Manufacturer: Texas Instruments; SizeZ_mm: 0.87; SizeX_mm: 1.65; SizeY_mm: 2.95; SizeArea_mm2: 4.8675; CompType: IC; SizeAreaWB_mm2: 10.4675; AEC Category: Q200
Y1 = CMP-0080365-2: Crystal, 20 MHz, 25 ppm, 18 pF, SMD; Manufacturer: ECS Inc.; Frequency Stability: 30 ppm; AEC Qualified: N; Frequency Tolerance: 25 ppm; AEC Category: Q200; TaMax_C: 85°C; Frequency_Fixed: 20MHz; TaMin_C: -40°C; Load Capacitance: 18 pF

## Sheet MCU072E1_ADC.SchDoc
size 431 x 279 mm; Date: Not shown in title block; ApprovedBy: Not shown in title block; CheckedBy: Not shown in title block; Author: Not shown in title block; CompanyName: Not shown in title block; DrawnBy: Cody Watkins; Engineer: Not shown in title block; Organization: Not shown in title block; Address1: Not shown in title block; Address2: Not shown in title block; Address3: Not shown in title block; Address4: Not shown in title block; DocumentNumber: 4; Revision: Use project parameter SCH_Rev; SheetNumber: 4; SheetTotal: 7; PageSetup: Record=PageOptions¦CenterHorizontal=True¦CenterVertical=True¦PrintScale=1.00¦XCorrection=1.00¦YCorrection=1.00¦PrintKind=0¦BorderSize=5000000¦LeftOffset=0¦BottomOffset=0¦Orientation=2¦PaperLength=1000¦PaperWidth=1000¦Scale=100¦PaperSource=15¦PrintQuality=600¦MediaType=1¦DitherType=10¦PaperKind=Letter¦PrintScaleMode=1
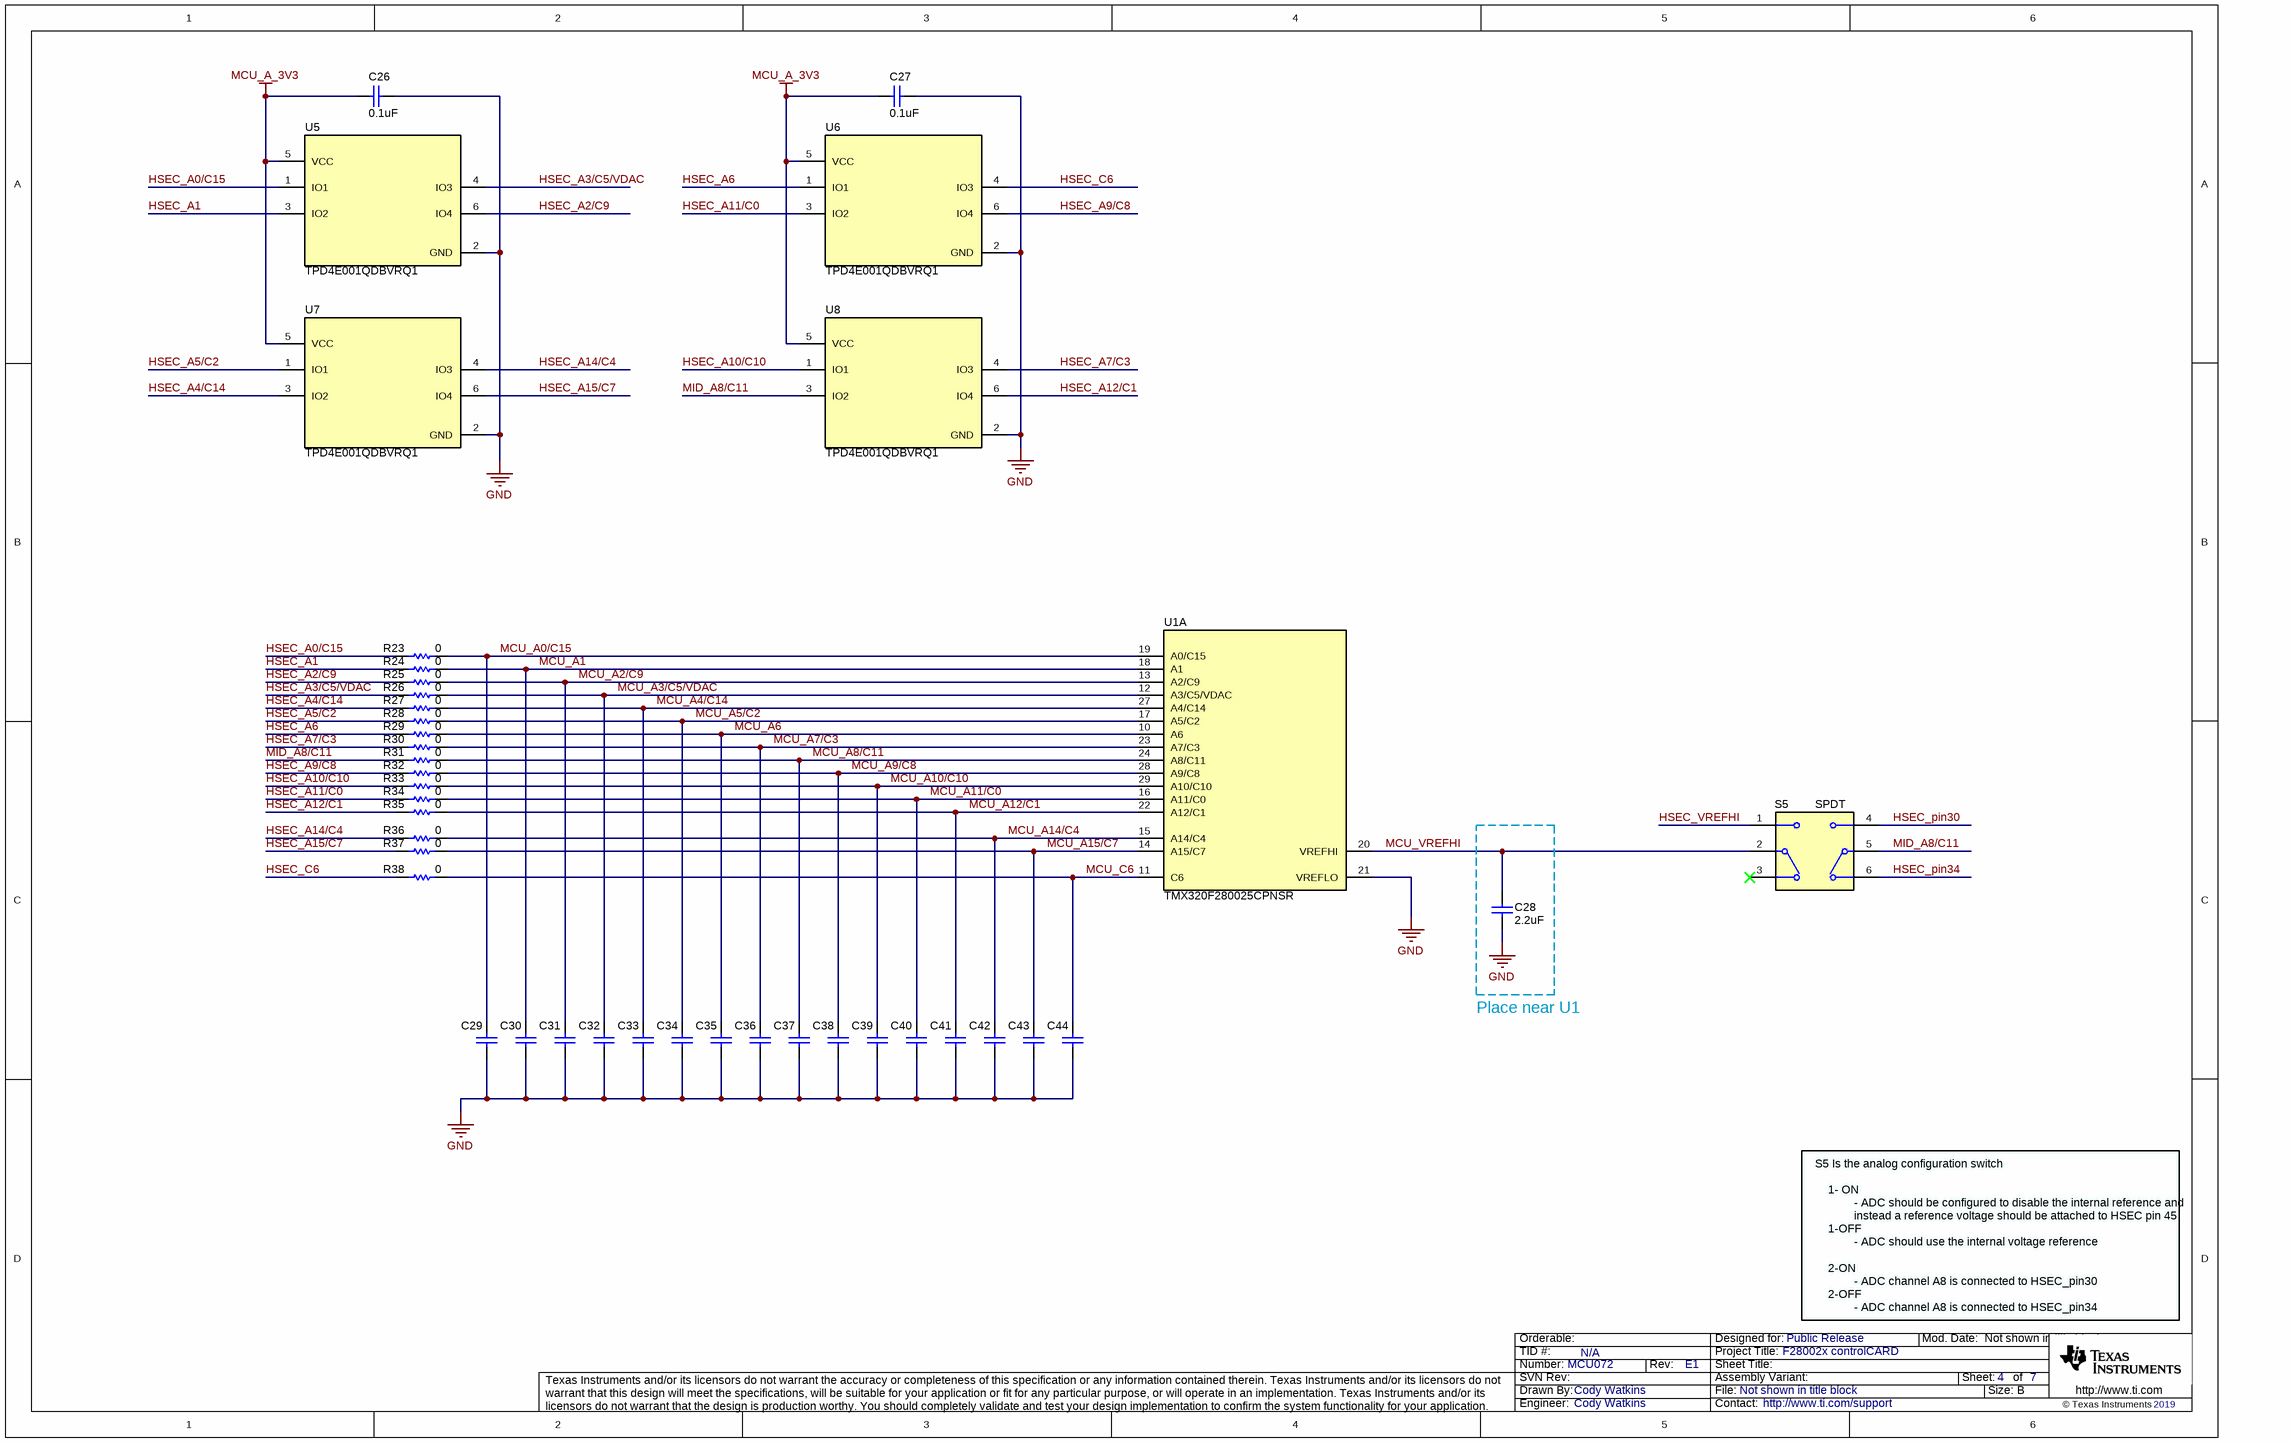
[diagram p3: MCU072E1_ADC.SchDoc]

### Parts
C26  ValueDisplayed: 0.1uF  [0402]  (hidden comment: 885012105010)
C27  ValueDisplayed: 0.1uF  [0402]  (hidden comment: 885012105010)
C28  ValueDisplayed: 2.2uF  [0603]  (hidden comment: CGA3E3X5R1A225K080AB)
C29  GRM188R71C104KA01D  [0603]  (value not drawn)
C30  GRM188R71C104KA01D  [0603]  (value not drawn)
C31  GRM188R71C104KA01D  [0603]  (value not drawn)
C32  GRM188R71C104KA01D  [0603]  (value not drawn)
C33  GRM188R71C104KA01D  [0603]  (value not drawn)
C34  GRM188R71C104KA01D  [0603]  (value not drawn)
C35  GRM188R71C104KA01D  [0603]  (value not drawn)
C36  GRM188R71C104KA01D  [0603]  (value not drawn)
C37  GRM188R71C104KA01D  [0603]  (value not drawn)
C38  GRM188R71C104KA01D  [0603]  (value not drawn)
C39  GRM188R71C104KA01D  [0603]  (value not drawn)
C40  GRM188R71C104KA01D  [0603]  (value not drawn)
C41  GRM188R71C104KA01D  [0603]  (value not drawn)
C42  GRM188R71C104KA01D  [0603]  (value not drawn)
C43  GRM188R71C104KA01D  [0603]  (value not drawn)
C44  GRM188R71C104KA01D  [0603]  (value not drawn)
R23  ValueDisplayed: 0  [0603]  (hidden comment: CRCW06030000Z0EA)
R24  ValueDisplayed: 0  [0603]  (hidden comment: CRCW06030000Z0EA)
R25  ValueDisplayed: 0  [0603]  (hidden comment: CRCW06030000Z0EA)
R26  ValueDisplayed: 0  [0603]  (hidden comment: CRCW06030000Z0EA)
R27  ValueDisplayed: 0  [0603]  (hidden comment: CRCW06030000Z0EA)
R28  ValueDisplayed: 0  [0603]  (hidden comment: CRCW06030000Z0EA)
R29  ValueDisplayed: 0  [0603]  (hidden comment: CRCW06030000Z0EA)
R30  ValueDisplayed: 0  [0603]  (hidden comment: CRCW06030000Z0EA)
R31  ValueDisplayed: 0  [0603]  (hidden comment: CRCW06030000Z0EA)
R32  ValueDisplayed: 0  [0603]  (hidden comment: CRCW06030000Z0EA)
R33  ValueDisplayed: 0  [0603]  (hidden comment: CRCW06030000Z0EA)
R34  ValueDisplayed: 0  [0603]  (hidden comment: CRCW06030000Z0EA)
R35  ValueDisplayed: 0  [0603]  (hidden comment: CRCW06030000Z0EA)
R36  ValueDisplayed: 0  [0603]  (hidden comment: CRCW06030000Z0EA)
R37  ValueDisplayed: 0  [0603]  (hidden comment: CRCW06030000Z0EA)
R38  ValueDisplayed: 0  [0603]  (hidden comment: CRCW06030000Z0EA)
S5  Circuit: SPDT  [SW_CAS-D20TA]  (hidden comment: CAS-D20TA)
U1  TMX320F280025CPNSR  [PN0080A_N]  (part A of 4)
U5  TPD4E001QDBVRQ1  [DBV0006A_N]
U6  TPD4E001QDBVRQ1  [DBV0006A_N]
U7  TPD4E001QDBVRQ1  [DBV0006A_N]
U8  TPD4E001QDBVRQ1  [DBV0006A_N]

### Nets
GND: C26.2 C27.2 C28.1 C29.2 C30.2 C31.2 C32.2 C33.2 C34.2 C35.2 C36.2 C37.2 C38.2 C39.2 C40.2 C41.2 C42.2 C43.2 C44.2 U1.21(VREFLO) U5.2(GND) U6.2(GND) U7.2(GND) U8.2(GND)
MCU_A_3V3: C26.1 C27.1 U5.5(VCC) U6.5(VCC) U7.5(VCC) U8.5(VCC)
HSEC_A0/C15: R23.2 U5.1(IO1)
HSEC_A1: R24.2 U5.3(IO2)
HSEC_A2/C9: R25.2 U5.6(IO4)
HSEC_A3/C5/VDAC: R26.2 U5.4(IO3)
HSEC_A4/C14: R27.2 U7.3(IO2)
HSEC_A5/C2: R28.2 U7.1(IO1)
HSEC_A6: R29.2 U6.1(IO1)
HSEC_A7/C3: R30.2 U8.4(IO3)
HSEC_A9/C8: R32.2 U6.6(IO4)
HSEC_A10/C10: R33.2 U8.1(IO1)
HSEC_A11/C0: R34.2 U6.3(IO2)
HSEC_A12/C1: R35.2 U8.6(IO4)
HSEC_A14/C4: R36.2 U7.4(IO3)
HSEC_A15/C7: R37.2 U7.6(IO4)
HSEC_C6: R38.2 U6.4(IO3)
HSEC_pin30: S5.4
HSEC_pin34: S5.6
HSEC_VREFHI: S5.1
MCU_A0/C15: C29.1 R23.1 U1.19(A0/C15)
MCU_A1: C30.1 R24.1 U1.18(A1)
MCU_A2/C9: C31.1 R25.1 U1.13(A2/C9)
MCU_A3/C5/VDAC: C32.1 R26.1 U1.12(A3/C5/VDAC)
MCU_A4/C14: C33.1 R27.1 U1.27(A4/C14)
MCU_A5/C2: C34.1 R28.1 U1.17(A5/C2)
MCU_A6: C35.1 R29.1 U1.10(A6)
MCU_A7/C3: C36.1 R30.1 U1.23(A7/C3)
MCU_A8/C11: C37.1 R31.1 U1.24(A8/C11)
MCU_A9/C8: C38.1 R32.1 U1.28(A9/C8)
MCU_A10/C10: C39.1 R33.1 U1.29(A10/C10)
MCU_A11/C0: C40.1 R34.1 U1.16(A11/C0)
MCU_A12/C1: C41.1 R35.1 U1.22(A12/C1)
MCU_A14/C4: C42.1 R36.1 U1.15(A14/C4)
MCU_A15/C7: C43.1 R37.1 U1.14(A15/C7)
MCU_C6: C44.1 R38.1 U1.11(C6)
MCU_VREFHI: C28.2 S5.2(C) U1.20(VREFHI)
MID_A8/C11: R31.2 S5.5(C) U8.3(IO2)

Not connected (* = marked no-connect by the designer): S5 3*

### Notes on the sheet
- Place near U1
- S5 Is the analog configuration switch
- 1- ON
- - ADC should be configured to disable the internal reference and
- 1-OFF
- 2-ON
- - ADC should use the internal voltage reference
- instead a reference voltage should be attached to HSEC pin 45
- 2-OFF
- - ADC channel A8 is connected to HSEC_pin30
- - ADC channel A8 is connected to HSEC_pin34

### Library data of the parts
C26 C27 = CMP-0006221-2: as C9 on sheet MCU072E1_Power
C28 = CMP-0007091-5: as C10 on sheet MCU072E1_Power
C29-C35 C37-C44 = CMP-0007378-5: CAP, CERM, 0.1 uF, 16 V, +/- 10%, X7R, 0603; Manufacturer: MuRata; Polarized: N; Value: 0.1uF; U/M: EA; Cap_F: 100nF; Value1: Unknown; VDC_V: 16V; TaMin_C: -55°C; TaMax_C: 125°C; SizeArea_mm2: 1.28; SizeAreaWB_mm2: 4.68; SizeX_mm: 1.6; SizeY_mm: 0.8; SizeZ_mm: 1; AEC Category: Q200
C36 = CMP-0007378-5: CAP, CERM, 0.1 uF, 16 V, +/- 10%, X7R, 0603; Manufacturer: MuRata; Polarized: N; CompType: Capacitor; Value: 0.1uF; U/M: EA; Cap_F: 100nF; Value1: Unknown; VDC_V: 16V; TaMin_C: -55°C; TaMax_C: 125°C; SizeArea_mm2: 1.28; SizeAreaWB_mm2: 4.68; SizeX_mm: 1.6; SizeY_mm: 0.8; SizeZ_mm: 1; AEC Category: Q200
R23-R38 = CMP-0025697-4: as R3 on sheet MCU072E1_GPIO
S5 = CMP-0002233-1: as S1 on sheet MCU072E1_GPIO
U1 = CMP-0750188-2: as U1 on sheet MCU072E1_GPIO
U5-U8 = CMP-0066599-1: Automotive Low-Capacitance 4-Channel +/-15-kV ESD Protection Array for High-Speed Data Interfaces, DBV0006A (SOT-23-6); Manufacturer: Texas Instruments; CompType: IC; U/M: EA; SizeArea_mm2: 8.12; SizeAreaWB_mm2: 14.82; SizeX_mm: 2.8; SizeY_mm: 2.9; SizeZ_mm: 1.45

## Sheet MCU072E1_Emulator_Hardware.SchDoc
size 431 x 279 mm; Date: Not shown in title block; ApprovedBy: Not shown in title block; CheckedBy: Not shown in title block; Author: Not shown in title block; CompanyName: Not shown in title block; DrawnBy: Cody Watkins; Engineer: Not shown in title block; Organization: Not shown in title block; Address1: Not shown in title block; Address2: Not shown in title block; Address3: Not shown in title block; Address4: Not shown in title block; DocumentNumber: 5; Revision: Use project parameter SCH_Rev; SheetNumber: 5; SheetTotal: 7; PageSetup: Record=PageOptions¦CenterHorizontal=True¦CenterVertical=True¦PrintScale=1.00¦XCorrection=1.00¦YCorrection=1.00¦PrintKind=0¦BorderSize=5000000¦LeftOffset=0¦BottomOffset=0¦Orientation=2¦PaperLength=1000¦PaperWidth=1000¦Scale=100¦PaperSource=15¦PrintQuality=600¦MediaType=1¦DitherType=10¦PaperKind=Letter¦PrintScaleMode=1
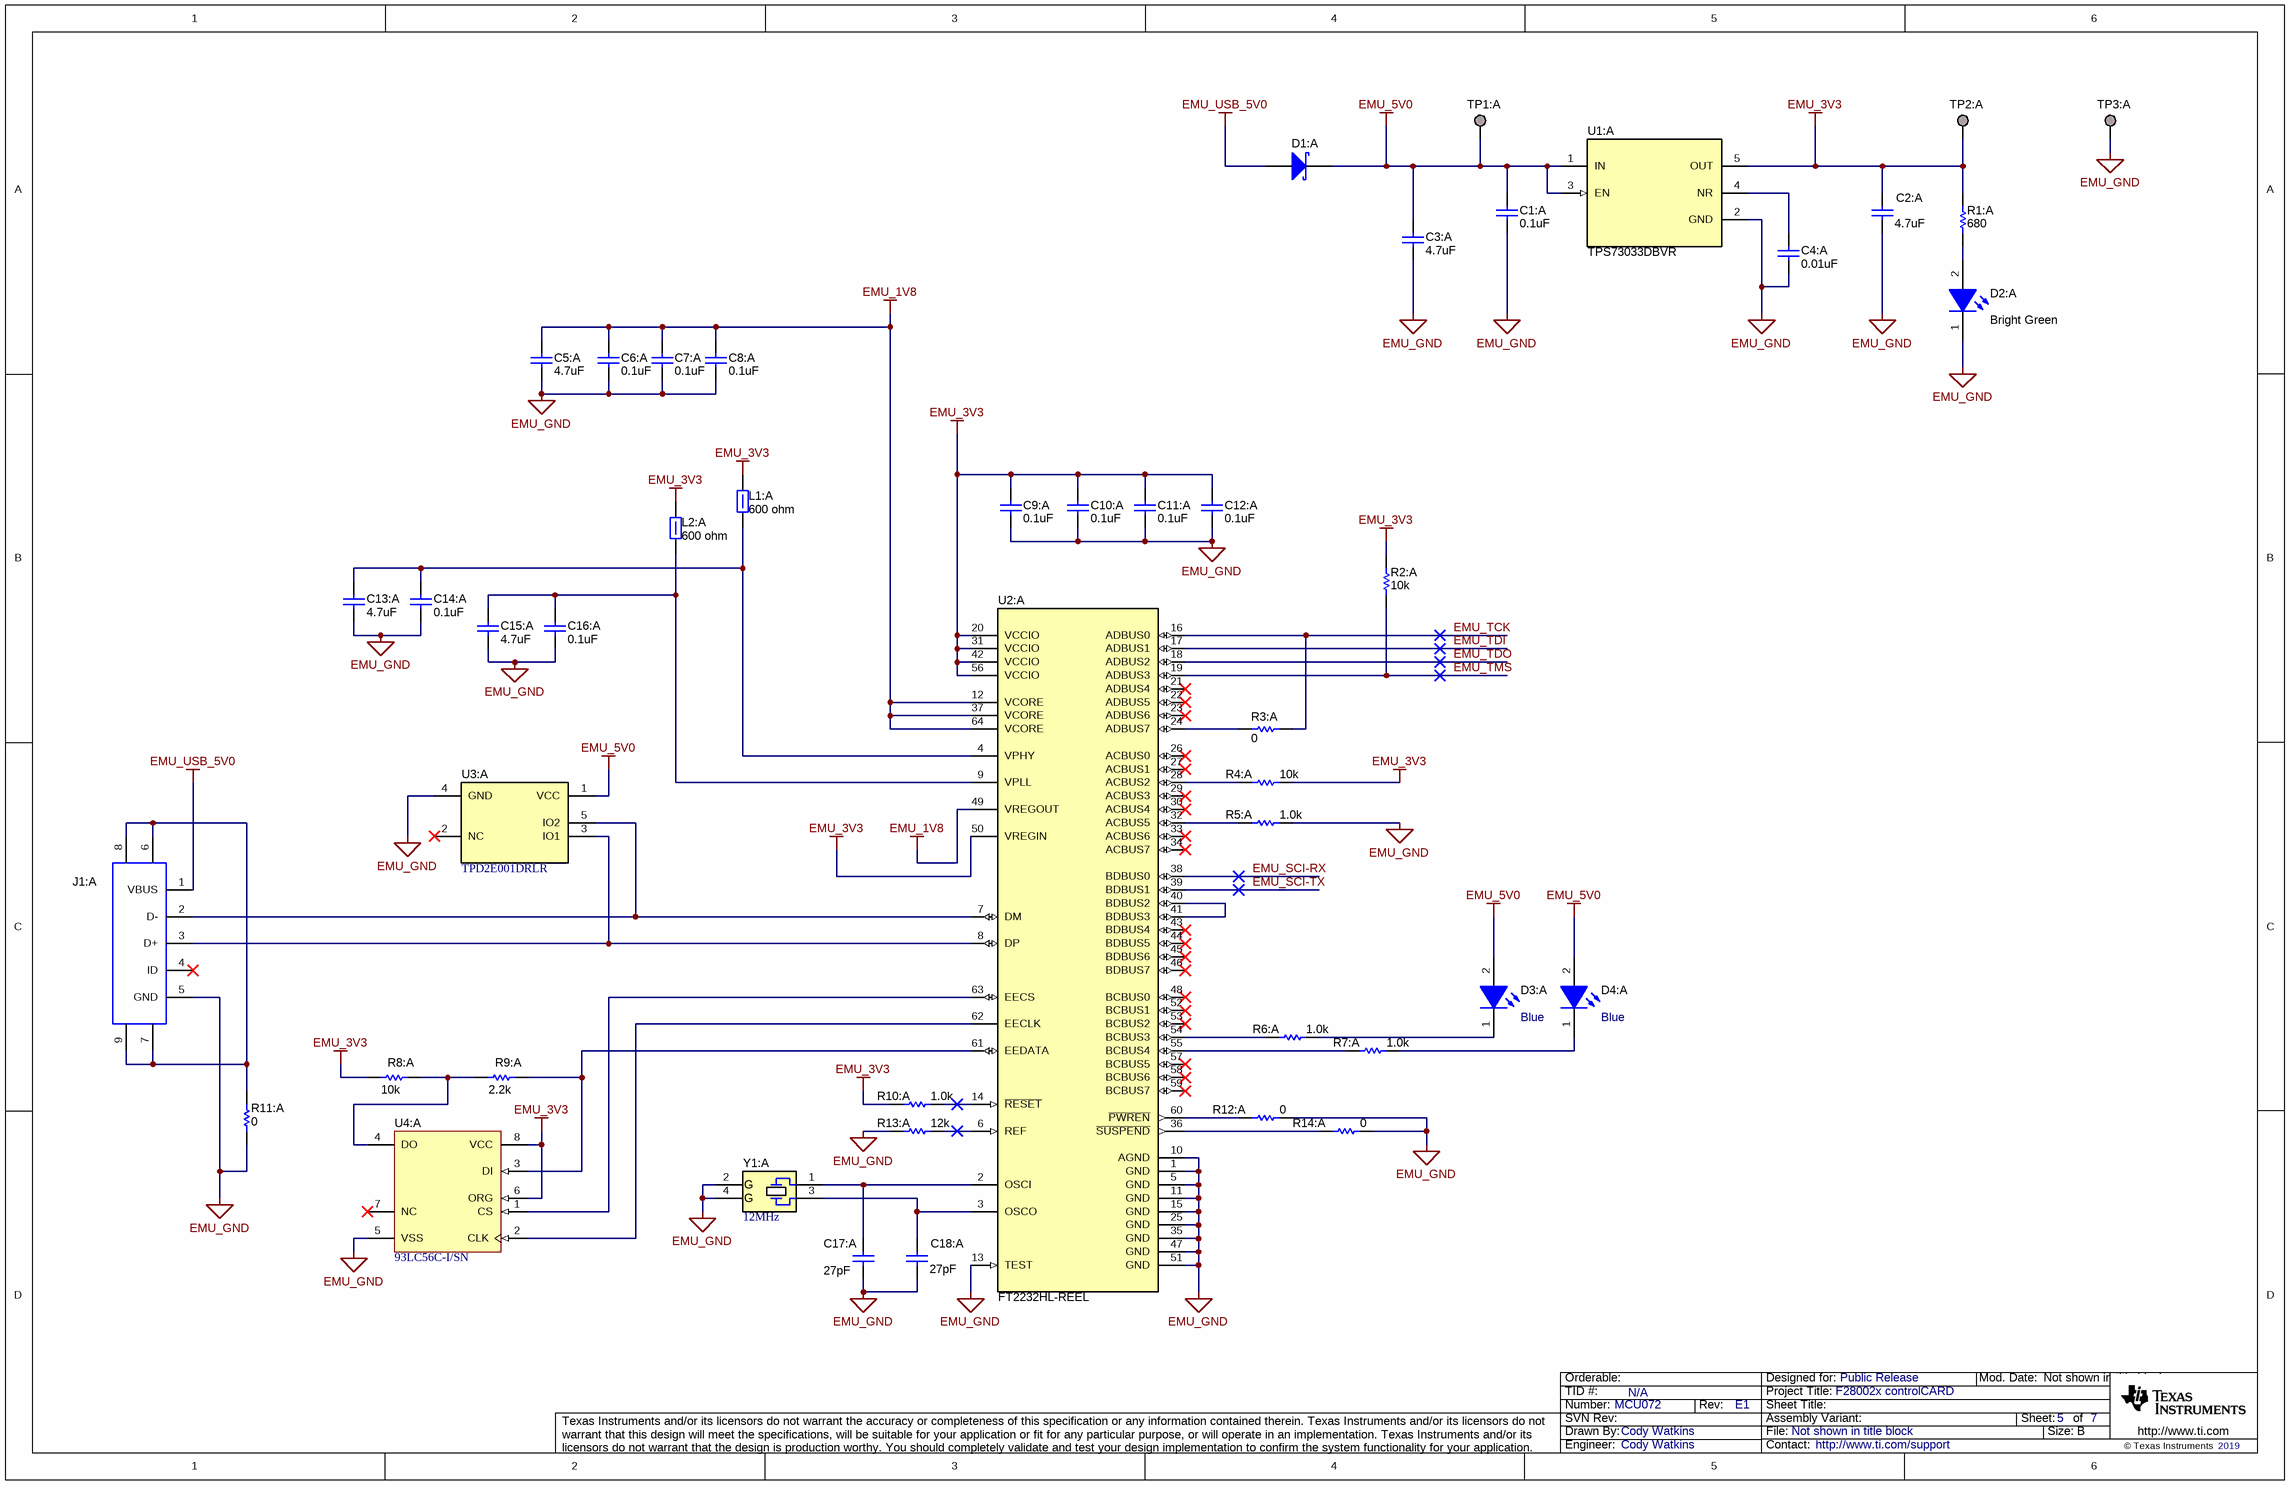
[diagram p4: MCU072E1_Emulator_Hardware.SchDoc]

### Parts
C1:A  ValueDisplayed: 0.1uF  [0402]  (hidden comment: 885012105010)
C2:A  ValueDisplayed: 4.7uF  [0603]  (hidden comment: C0603C475K9PACTU)
C3:A  ValueDisplayed: 4.7uF  [0603]  (hidden comment: C0603C475K9PACTU)
C4:A  ValueDisplayed: 0.01uF  [0402]  (hidden comment: 0402ZC103KAT2A)
C5:A  ValueDisplayed: 4.7uF  [0603]  (hidden comment: C0603C475K9PACTU)
C6:A  ValueDisplayed: 0.1uF  [0402]  (hidden comment: 885012105010)
C7:A  ValueDisplayed: 0.1uF  [0402]  (hidden comment: 885012105010)
C8:A  ValueDisplayed: 0.1uF  [0402]  (hidden comment: 885012105010)
C9:A  ValueDisplayed: 0.1uF  [0402]  (hidden comment: 885012105010)
C10:A  ValueDisplayed: 0.1uF  [0402]  (hidden comment: 885012105010)
C11:A  ValueDisplayed: 0.1uF  [0402]  (hidden comment: 885012105010)
C12:A  ValueDisplayed: 0.1uF  [0402]  (hidden comment: CL05B104KP5NNNC)
C13:A  ValueDisplayed: 4.7uF  [0603]  (hidden comment: C0603C475K9PACTU)
C14:A  ValueDisplayed: 0.1uF  [0402]  (hidden comment: 885012105010)
C15:A  ValueDisplayed: 4.7uF  [0603]  (hidden comment: C0603C475K9PACTU)
C16:A  ValueDisplayed: 0.1uF  [0402]  (hidden comment: 885012105010)
C17:A  ValueDisplayed: 27pF  [0402]  (hidden comment: C0402C270J5GACTU)
C18:A  ValueDisplayed: 27pF  [0402]  (hidden comment: C0402C270J5GACTU)
D1:A  MBRM110ET1G  [POWERMITE]  (value not drawn)
D2:A  value Bright Green  [WL-SMCW_Green_0805]  (hidden comment: 150080VS75000)
D3:A  value Blue  [WL-SMCW_Blue_0805]  (hidden comment: 150080BS75000)
D4:A  value Blue  [WL-SMCW_Blue_0805]  (hidden comment: 150080BS75000)
J1:A  65100516121  [Wurth_65100516121]  (value not drawn)
L1:A  value 600 ohm  [0805_HV]  (hidden comment: HZ0805E601R-10)
L2:A  value 600 ohm  [0805_HV]  (hidden comment: HZ0805E601R-10)
R1:A  ValueDisplayed: 680  [0402]  (hidden comment: CRCW0402680RJNED)
R2:A  ValueDisplayed: 10k  [0402]  (hidden comment: CRCW040210K0JNED)
R3:A  ValueDisplayed: 0  [0402]  (hidden comment: CRCW04020000Z0ED)
R4:A  ValueDisplayed: 10k  [0402]  (hidden comment: CRCW040210K0JNED)
R5:A  ValueDisplayed: 1.0k  [0402]  (hidden comment: CRCW04021K00JNED)
R6:A  ValueDisplayed: 1.0k  [0402]  (hidden comment: CRCW04021K00JNED)
R7:A  ValueDisplayed: 1.0k  [0402]  (hidden comment: CRCW04021K00JNED)
R8:A  ValueDisplayed: 10k  [0402]  (hidden comment: CRCW040210K0JNED)
R9:A  ValueDisplayed: 2.2k  [0402]  (hidden comment: CRCW04022K20JNED)
R10:A  ValueDisplayed: 1.0k  [0402]  (hidden comment: CRCW04021K00JNED)
R11:A  ValueDisplayed: 0  [0402]  (hidden comment: CRCW04020000Z0ED)
R12:A  ValueDisplayed: 0  [0402]  (hidden comment: CRCW04020000Z0ED)
R13:A  ValueDisplayed: 12k  [0402]  (hidden comment: CRCW040212K0JNED)
R14:A  ValueDisplayed: 0  [0402]  (hidden comment: CRCW04020000Z0ED)
TP1:A  TESTPOINT  [TP_50MIL-25MILHOLE]  (value not drawn)  (no BOM)
TP2:A  TESTPOINT  [TP_50MIL-25MILHOLE]  (value not drawn)  (no BOM)
TP3:A  TESTPOINT  [TP_50MIL-25MILHOLE]  (value not drawn)  (no BOM)
U1:A  TPS73033DBVR  [DBV0005A_N]
U2:A  FT2232HL-REEL  [LQFP64_N]
U3:A  TPD2E001DRLR  [DRL0005A]
U4:A  93LC56C-I/SN  [SOIC-8]
Y1:A  12MHz  [ECS_ECX-53B]

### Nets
EMU_1V8: C5:A.2 C6:A.2 C7:A.2 C8:A.2 U2:A.12(VCORE) U2:A.37(VCORE) U2:A.49(VREGOUT) U2:A.64(VCORE)
EMU_3V3: C2:A.1 C9:A.2 C10:A.2 C11:A.2 C12:A.2 L1:A.2 L2:A.2 R1:A.1 R2:A.2 R4:A.2 R8:A.1 R10:A.1 TP2:A.1 U1:A.5(OUT) U2:A.20(VCCIO) U2:A.31(VCCIO) U2:A.42(VCCIO) U2:A.50(VREGIN) U2:A.56(VCCIO) U4:A.6(ORG) U4:A.8(VCC)
EMU_5V0: C1:A.2 C3:A.1 D1:A.1(K) D3:A.2(A) D4:A.2(A) TP1:A.1 U1:A.1(IN) U1:A.3(EN) U3:A.1(VCC)
EMU_GND: C1:A.1 C2:A.2 C3:A.2 C4:A.1 C5:A.1 C6:A.1 C7:A.1 C8:A.1 C9:A.1 C10:A.1 C11:A.1 C12:A.1 C13:A.2 C14:A.1 C15:A.2 C16:A.1 C17:A.1 C18:A.1 D2:A.1(K) J1:A.5(GND) R5:A.2 R11:A.2 R12:A.1 R13:A.1 R14:A.1 TP3:A.1 U1:A.2(GND) U2:A.1(GND) U2:A.5(GND) U2:A.10(AGND) U2:A.11(GND) U2:A.13(TEST) U2:A.15(GND) U2:A.25(GND) U2:A.35(GND) U2:A.47(GND) U2:A.51(GND) U3:A.4(GND) U4:A.5(VSS) Y1:A.2(GND) Y1:A.4(GND)
EMU_USB_5V0: D1:A.2(A) J1:A.1(VBUS)
EMU_SCI-RX: U2:A.38(BDBUS0)
EMU_SCI-TX: U2:A.39(BDBUS1)
EMU_TCK: R3:A.1 U2:A.16(ADBUS0)
EMU_TDI: U2:A.17(ADBUS1)
EMU_TDO: U2:A.18(ADBUS2)
EMU_TMS: R2:A.1 U2:A.19(ADBUS3)
NetC4:A_2: C4:A.2 U1:A.4(NR)
NetC13:A_1: C13:A.1 C14:A.2 L1:A.1 U2:A.4(VPHY)
NetC15:A_1: C15:A.1 C16:A.2 L2:A.1 U2:A.9(VPLL)
NetC17:A_2: C17:A.2 U2:A.2(OSCI) Y1:A.1
NetC18:A_2: C18:A.2 U2:A.3(OSCO) Y1:A.3
NetD2:A_2: D2:A.2(A) R1:A.2
NetD3:A_1: D3:A.1(K) R6:A.2
NetD4:A_1: D4:A.1(K) R7:A.2
NetJ1:A_2: J1:A.2(D-) U2:A.7(DM) U3:A.5(IO2)
NetJ1:A_3: J1:A.3(D+) U2:A.8(DP) U3:A.3(IO1)
NetJ1:A_6: J1:A.6 J1:A.7 J1:A.8 J1:A.9 R11:A.1
NetR3:A_2: R3:A.2 U2:A.24(ADBUS7)
NetR4:A_1: R4:A.1 U2:A.28(ACBUS2)
NetR5:A_1: R5:A.1 U2:A.32(ACBUS5)
NetR6:A_1: R6:A.1 U2:A.54(BCBUS3)
NetR7:A_1: R7:A.1 U2:A.55(BCBUS4)
NetR8:A_2: R8:A.2 R9:A.1 U4:A.4(DO)
NetR9:A_2: R9:A.2 U2:A.61(EEDATA) U4:A.3(DI)
NetR10:A_2: R10:A.2 U2:A.14(~{RESET})
NetR12:A_2: R12:A.2 U2:A.60(~{PWREN})
NetR13:A_2: R13:A.2 U2:A.6(REF)
NetR14:A_2: R14:A.2 U2:A.36(~{SUSPEND})
NetU2:A_40: U2:A.40(BDBUS2) U2:A.41(BDBUS3)
NetU2:A_62: U2:A.62(EECLK) U4:A.2(CLK)
NetU2:A_63: U2:A.63(EECS) U4:A.1(CS)

Not connected (* = marked no-connect by the designer): J1:A 4(ID)*; U2:A 21(ADBUS4)* 22(ADBUS5)* 23(ADBUS6)* 26(ACBUS0)* 27(ACBUS1)* 29(ACBUS3)* 30(ACBUS4)* 33(ACBUS6)* 34(ACBUS7)* 43(BDBUS4)* 44(BDBUS5)* 45(BDBUS6)* 46(BDBUS7)* 48(BCBUS0)* 52(BCBUS1)* 53(BCBUS2)* 57(BCBUS5)* 58(BCBUS6)* 59(BCBUS7)*; U3:A 2(NC)*; U4:A 7(NC)*

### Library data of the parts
C1:A C6:A C7:A C8:A C9:A C10:A C11:A C14:A C16:A = CMP-0006221-2: as C9 on sheet MCU072E1_Power
C2:A C3:A C5:A C13:A C15:A = CMP-0006950-5: CAP, CERM, 4.7 uF, 6.3 V, +/- 10%, X5R, 0603; Manufacturer: Kemet; Polarized: N; Value: 4.7uF; U/M: EA; Cap_F: 4.7µF; ESR_ohm: 6m; Value1: 0.006 ohm; VDC_V: 6.3V; IRMS_A: 7.24A; TaMin_C: -55°C; TaMax_C: 85°C; AEC Category: Q200; SizeArea_mm2: 1.28; SizeAreaWB_mm2: 4.68; SizeX_mm: 1.6; SizeY_mm: 0.8; SizeZ_mm: 1
C4:A = CMP-0006203-2: as C21 on sheet MCU072E1_Power
C12:A = CMP-0006343-2: CAP, CERM, 0.1 uF, 10 V, +/- 10%, X7R, 0402; Manufacturer: Samsung Electro-Mechanics; Polarized: N; Value: 0.1uF; U/M: EA; Cap_F: 100nF; Value1: Unknown; VDC_V: 10V; TaMin_C: -55°C; TaMax_C: 125°C; AEC Category: Q200; SizeArea_mm2: 0.5; SizeAreaWB_mm2: 3; SizeX_mm: 1; SizeZ_mm: 0.6
C17:A = CMP-0750098-1: CAP, CERM, 27 pF, 50 V,+/- 5%, C0G/NP0, 0402; Manufacturer: Kemet; Polarized: N; Value: 27pF; U/M: EA; Value2: 50V; TaMin_C: -55°C; TaMax_C: 125°C; AEC Category: Q200; SizeArea_mm2: 0.5; SizeAreaWB_mm2: 3; SizeX_mm: 1; SizeZ_mm: 0.6; Green_REACh: Passed; Green_Lifecycle: Active
C18:A = CMP-0750098-1: CAP, CERM, 27 pF, 50 V,+/- 5%, C0G/NP0, 0402; Manufacturer: Kemet; Polarized: N; Value: 27pF; U/M: EA; VDC_V: 50V; TaMin_C: -55°C; TaMax_C: 125°C; AEC Category: Q200; SizeArea_mm2: 0.5; SizeAreaWB_mm2: 3; SizeX_mm: 1; SizeZ_mm: 0.6; Green_Lifecycle: Active; Green_REACh: Passed
D1:A = CMP-0028747-2: Diode, Schottky, 10 V, 1 A, AEC-Q101, POWERMITE; Manufacturer: ON Semiconductor; Vf_V: 530mV; Value: 10V; Value1: 1A; Value2: 0.53V; TJmax_C: 150°C; AEC Category: Q101; AEC Qualified: Y; SizeAreaWB_mm2: 14.945; SizeArea_mm2: 7.995; SizeX_mm: 3.9; SizeY_mm: 2.05; SizeZ_mm: 1.15; Green_Lifecycle: Not Set; Green_REACh: Incomplete
D2:A = CMP-0002960-2: as D3 on sheet MCU072E1_Power
D3:A D4:A = CMP-0002959-3: LED, Blue, SMD; Manufacturer: Wurth Elektronik; Type: InGaN; Vf_V: 3.2V; Io_A: 20mA; Vr_V: 5V; Tjmax_C: 85°C; Power_TotalModule: 105mW; Value1: 0.105W; Angle: 140
J1:A = CMP-0054809-1: Connector, Receptacle, USB Mini B 2.0, SMT; Manufacturer: Wurth Elektronik; Pitch_mm: 0.8; Gender: Female; Row_Count: 1; ContactFinish: Gold; Current_A: 1A; Voltage_V: 30V; Cert_UL: Y; CNHeader: FALSE; CT: TRUE; Green_Lifecycle: Active; Green_REACh: Passed
L1:A L2:A = CMP-0003398-1: Ferrite Bead, 600 ohm @ 100 MHz, 0.5 A, 0805; Manufacturer: Laird-Signal Integrity Products; Imax_A: 5dA; DCR_ohm: 3d; Value1: 0.3 ohm; Value2: 0.5A; ZTyp@100MHz_Ohm: 600; SizeArea_mm2: 2.5; SizeAreaWB_mm2: 6.75; SizeX_mm: 2; SizeY_mm: 1.25; SizeZ_mm: 1.45
R1:A = CMP-0026962-3: RES, 680, 5%, 0.063 W, AEC-Q200 Grade 0, 0402; Manufacturer: Vishay-Dale; Value: 680; Value_Code: 680R; Power_W: 63mW; Value2: 0.063W; VDC_V: 50V; TempCo: 200 ppm/C; EIA_Code: E24; AEC Category: Q200; AEC Qualified: Y; AEC Grade: 0; SizeArea_mm2: 0.5; SizeX_mm: 1; SizeZ_mm: 0.6
R2:A R4:A R8:A = CMP-0026825-5: RES, 10 k, 5%, 0.063 W, AEC-Q200 Grade 0, 0402; Manufacturer: Vishay-Dale; Value: 10k; Value_Code: 10k0; Power_W: 63mW; Value2: 0.063W; VDC_V: 50V; TempCo: 200 ppm/C; EIA_Code: E24; AEC Category: Q200; AEC Qualified: Y; AEC Grade: 0; SizeArea_mm2: 0.5; SizeX_mm: 1; SizeZ_mm: 0.6
R3:A R11:A R12:A R14:A = CMP-0026822-3: RES, 0, 5%, 0.063 W, AEC-Q200 Grade 0, 0402; Manufacturer: Vishay-Dale; Value: 0; Value_Code: 0000; Power_W: 63mW; Value2: 0.063W; VDC_V: 50V; TempCo: 200 ppm/C; EIA_Code: E24; AEC Category: Q200; AEC Qualified: Y; SizeArea_mm2: 0.5; SizeX_mm: 1; SizeZ_mm: 0.6
R5:A R6:A R7:A R10:A = CMP-0026852-3: RES, 1.0 k, 5%, 0.063 W, AEC-Q200 Grade 0, 0402; Manufacturer: Vishay-Dale; Value: 1.0k; Res_ohm: 1k; Value_Code: 1k00; Power_W: 63mW; Value2: 0.063W; VDC_V: 50V; TempCo: 200 ppm/C; EIA_Code: E24; AEC Category: Q200; AEC Qualified: Y; AEC Grade: 0; SizeArea_mm2: 0.5; SizeX_mm: 1; SizeZ_mm: 0.6
R9:A = CMP-0026890-5: as R19 on sheet MCU072E1_Power
R13:A = CMP-0026834-3: RES, 12 k, 5%, 0.063 W, AEC-Q200 Grade 0, 0402; Manufacturer: Vishay-Dale; Value: 12k; Value_Code: 12k0; Power_W: 63mW; Value2: 0.063W; VDC_V: 50V; TempCo: 200 ppm/C; EIA_Code: E24; AEC Category: Q200; AEC Qualified: Y; AEC Grade: 0; SizeArea_mm2: 0.5; SizeX_mm: 1; SizeZ_mm: 0.6
TP1:A TP2:A TP3:A = CMP-0078143-2: TEST POINT.  No entry in BOM.
U1:A = CMP-0073823-1: Low-Noise, High PSRR, RF 200-mA Low-Dropout Linear Regulators, DBV0005A (SOT-23-5); Alternate PartNumber: TPS73033DBVT; Manufacturer: Texas Instruments; CompType: IC; U/M: EA; SizeArea_mm2: 8.12; SizeAreaWB_mm2: 14.82; SizeX_mm: 2.8; SizeY_mm: 2.9; SizeZ_mm: 1.45; Green_Lifecycle: Active; Green_REACh: Passed
U2:A = CMP-0004796-1: Dual High Speed USB To Multipurpose UART/FIFO IC, LQFP-64; Manufacturer: FTDI
U3:A = CMP-0043096-2: Low-Capacitance + / - 15 kV ESD-Protection Array for High-Speed Data Interfaces, 2 Channels, -40 to +85 degC, 5-pin SOT (DRL), Green (RoHS & no Sb/Br); Manufacturer: Texas Instruments; Breakdown Voltage(Min)(V): 11; IEC 61000-4-2 Air-Gap(+/- kV): 15; IEC 61000-4-2 Contact(+/- kV): 8; IO Capacitance(Typ)(pF): 1.5; IO Leakage Current(nA): 1; SubFamily: ESD Solution; USB High Speed: TRUE
U4:A = CMP-0005261-2: 2K Microwire Compatible Serial EEPROM, SOIC-8; Manufacturer: Microchip; SizeAreaWB_mm2: 55.131; SizeArea_mm2: 29.351; SizeX_mm: 5.99; SizeY_mm: 4.9; SizeZ_mm: 1.75
Y1:A = CMP-0004646-3: Crystal, 12 MHz, 20pF, SMD; PartNumber: ECS-120-20-30B-TR; Manufacturer: ECS Inc.; TaMin_C: -20°C; TaMax_C: 70°C; Frequency Stability: +/-50ppm

## Sheet MCU072E1_Emulator_Interface.SchDoc
size 431 x 279 mm; Date: Not shown in title block; ApprovedBy: Not shown in title block; CheckedBy: Not shown in title block; Author: Not shown in title block; CompanyName: Not shown in title block; DrawnBy: Cody Watkins; Engineer: Not shown in title block; Organization: Not shown in title block; Address1: Not shown in title block; Address2: Not shown in title block; Address3: Not shown in title block; Address4: Not shown in title block; DocumentNumber: 6; Revision: Use project parameter SCH_Rev; SheetNumber: 6; SheetTotal: 7; PageSetup: Record=PageOptions¦CenterHorizontal=True¦CenterVertical=True¦PrintScale=1.00¦XCorrection=1.00¦YCorrection=1.00¦PrintKind=0¦BorderSize=5000000¦LeftOffset=0¦BottomOffset=0¦Orientation=2¦PaperLength=1000¦PaperWidth=1000¦Scale=100¦PaperSource=15¦PrintQuality=600¦MediaType=1¦DitherType=10¦PaperKind=Letter¦PrintScaleMode=1
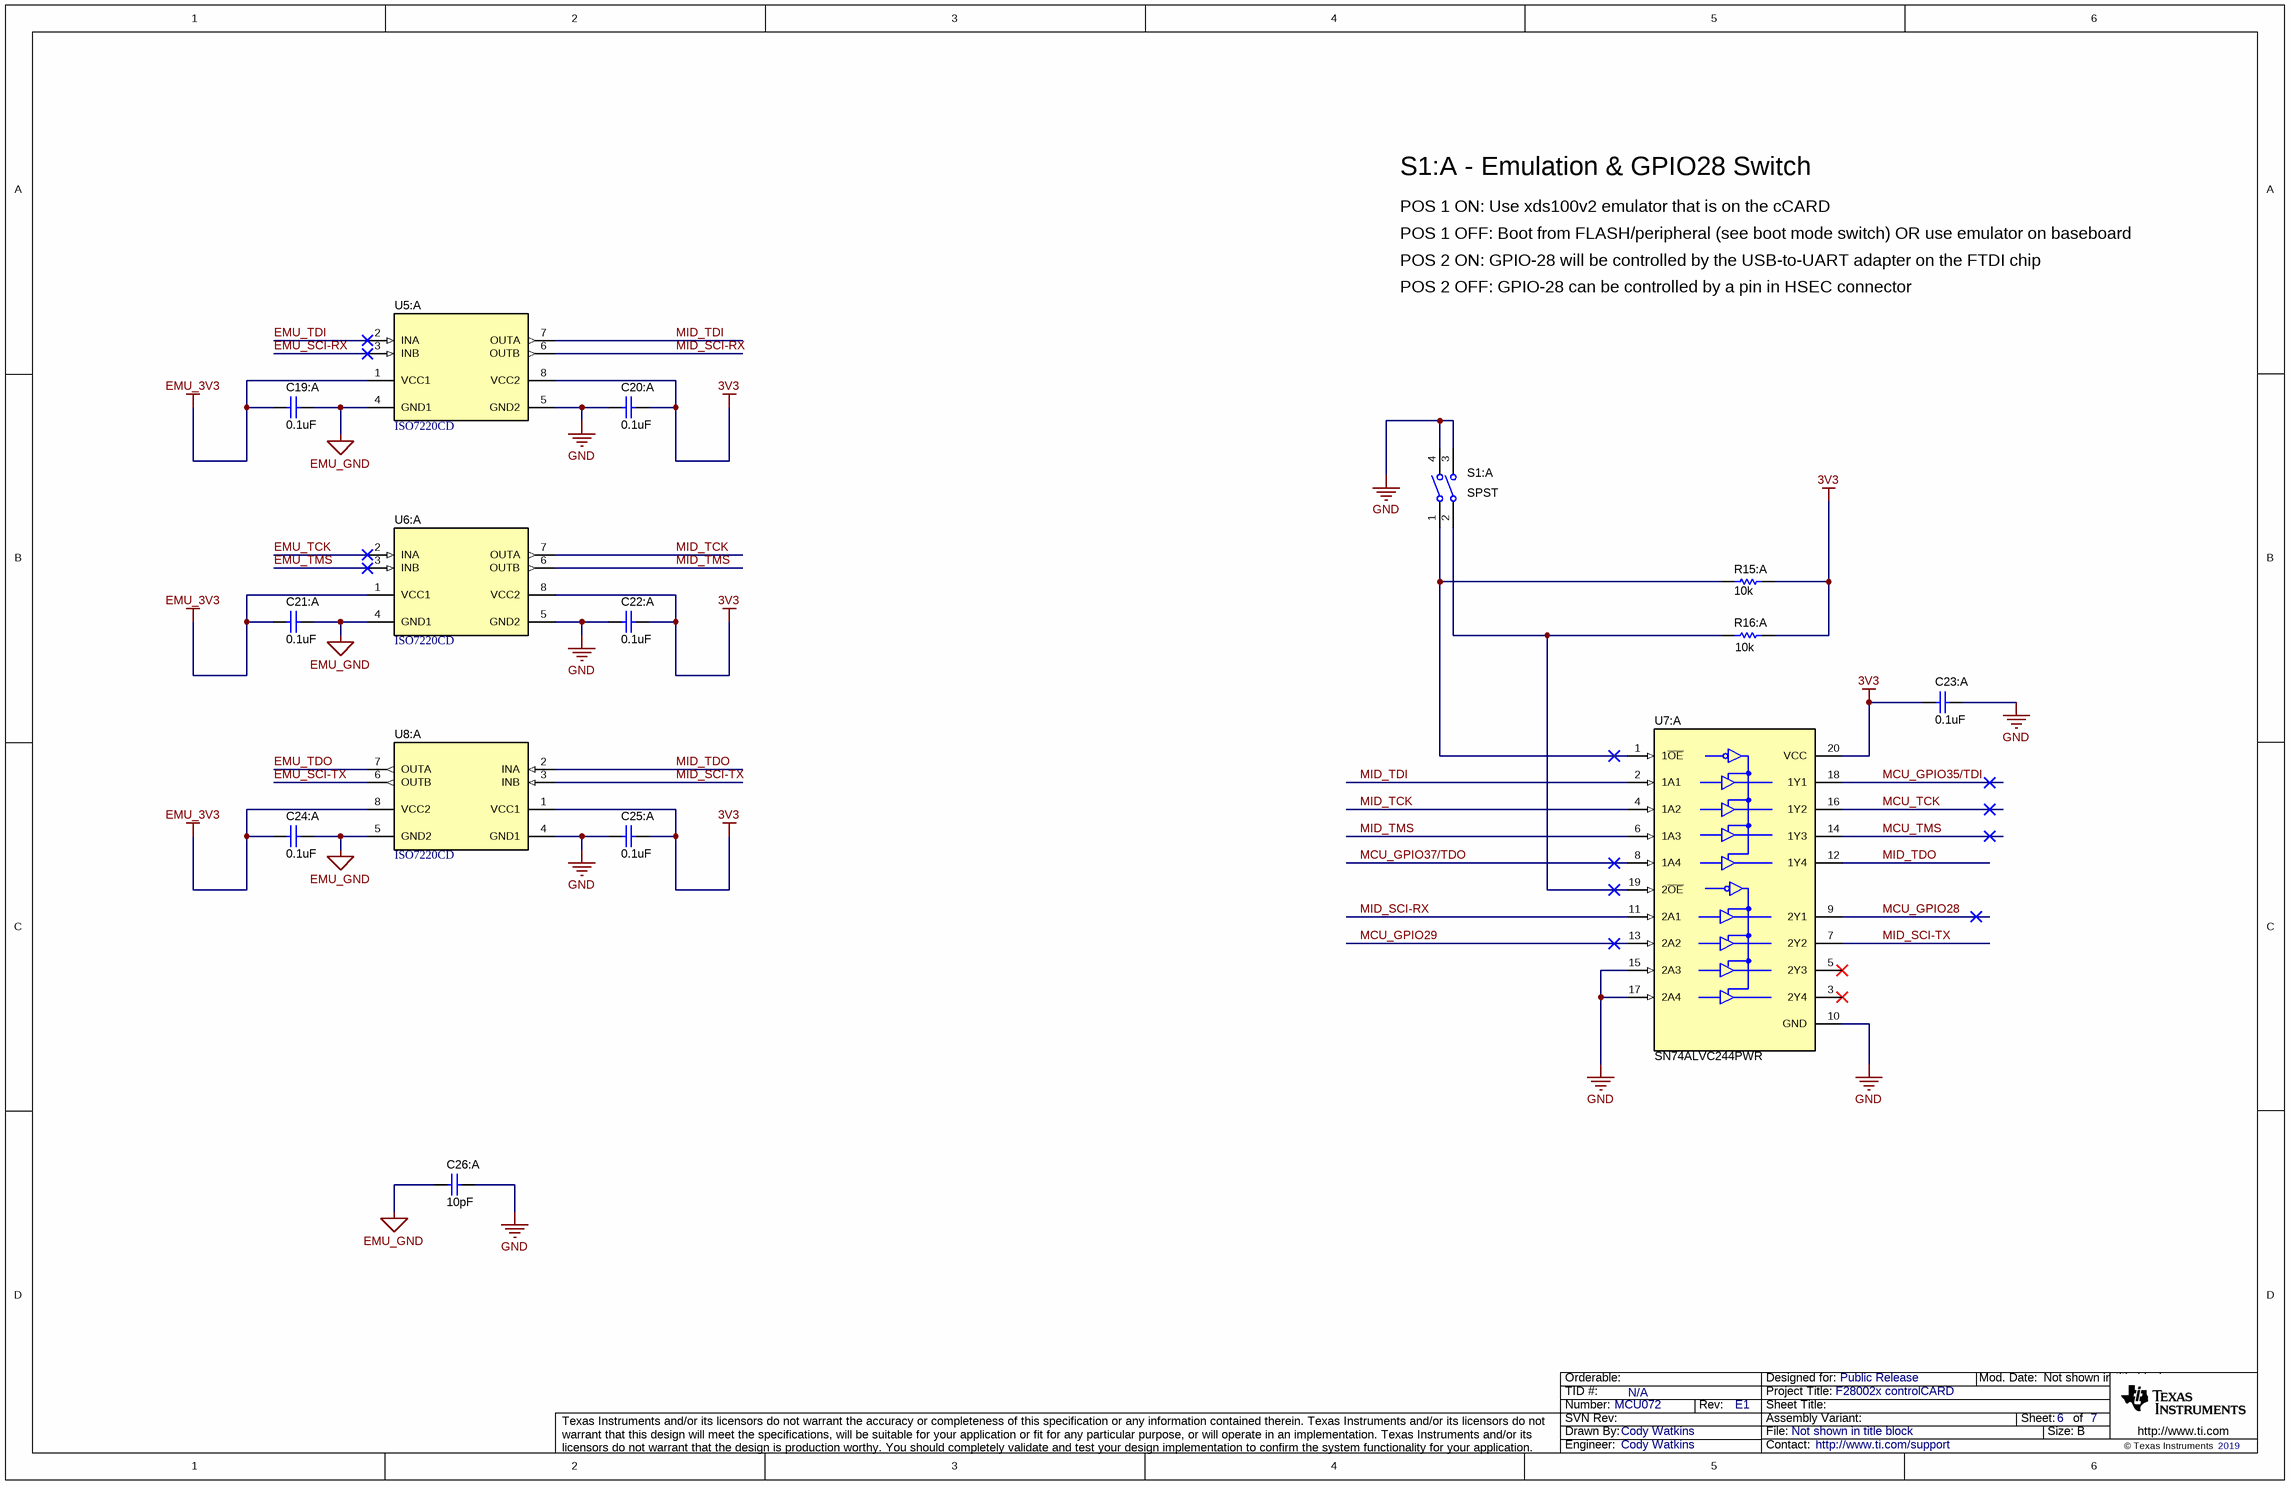
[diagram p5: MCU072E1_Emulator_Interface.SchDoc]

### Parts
C19:A  ValueDisplayed: 0.1uF  [0402]  (hidden comment: 885012105010)
C20:A  ValueDisplayed: 0.1uF  [0402]  (hidden comment: 885012105010)
C21:A  ValueDisplayed: 0.1uF  [0402]  (hidden comment: 885012105010)
C22:A  ValueDisplayed: 0.1uF  [0402]  (hidden comment: 885012105010)
C23:A  ValueDisplayed: 0.1uF  [0402]  (hidden comment: 885012105010)
C24:A  ValueDisplayed: 0.1uF  [0402]  (hidden comment: 885012105010)
C25:A  ValueDisplayed: 0.1uF  [0402]  (hidden comment: 885012105010)
C26:A  ValueDisplayed: 10pF  [1812_180]  (hidden comment: C1812C100JHGACTU)
R15:A  ValueDisplayed: 10k  [0402]  (hidden comment: CRCW040210K0JNED)
R16:A  ValueDisplayed: 10k  [0402]  (hidden comment: CRCW040210K0JNED)
S1:A  Circuit: SPST  [SW_218-2LP]  (hidden comment: 218-2LPST)
U5:A  ISO7220CD  [D0008B_N]
U6:A  ISO7220CD  [D0008B_N]
U7:A  SN74ALVC244PWR  [PW0020A_N]
U8:A  ISO7220CD  [D0008B_N]

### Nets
3V3: C20:A.1 C22:A.1 C23:A.2 C25:A.1 R15:A.2 R16:A.2 U5:A.8(VCC2) U6:A.8(VCC2) U7:A.20(VCC) U8:A.1(VCC1)
EMU_3V3: C19:A.2 C21:A.2 C24:A.2 U5:A.1(VCC1) U6:A.1(VCC1) U8:A.8(VCC2)
EMU_GND: C19:A.1 C21:A.1 C24:A.1 C26:A.2 U5:A.4(GND1) U6:A.4(GND1) U8:A.5(GND2)
GND: C20:A.2 C22:A.2 C23:A.1 C25:A.2 C26:A.1 S1:A.3 S1:A.4 U5:A.5(GND2) U6:A.5(GND2) U7:A.10(GND) U7:A.15(2A3) U7:A.17(2A4) U8:A.4(GND1)
EMU_SCI-RX: U5:A.3(INB)
EMU_SCI-TX: U8:A.6(OUTB)
EMU_TCK: U6:A.2(INA)
EMU_TDI: U5:A.2(INA)
EMU_TDO: U8:A.7(OUTA)
EMU_TMS: U6:A.3(INB)
MCU_GPIO28: U7:A.9(2Y1)
MCU_GPIO29: U7:A.13(2A2)
MCU_GPIO35/TDI: U7:A.18(1Y1)
MCU_GPIO37/TDO: U7:A.8(1A4)
MCU_TCK: U7:A.16(1Y2)
MCU_TMS: U7:A.14(1Y3)
MID_SCI-RX: U5:A.6(OUTB) U7:A.11(2A1)
MID_SCI-TX: U7:A.7(2Y2) U8:A.3(INB)
MID_TCK: U6:A.7(OUTA) U7:A.4(1A2)
MID_TDI: U5:A.7(OUTA) U7:A.2(1A1)
MID_TDO: U7:A.12(1Y4) U8:A.2(INA)
MID_TMS: U6:A.6(OUTB) U7:A.6(1A3)
NetR15:A_1: R15:A.1 S1:A.1 U7:A.1(1~{OE})
NetR16:A_1: R16:A.1 S1:A.2 U7:A.19(2~{OE})

Not connected (* = marked no-connect by the designer): U7:A 3(2Y4)* 5(2Y3)*

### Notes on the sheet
- S1:A - Emulation & GPIO28 Switch
- POS 1 ON: Use xds100v2 emulator that is on the cCARD
- POS 1 OFF: Boot from FLASH/peripheral (see boot mode switch) OR use emulator on baseboard
- POS 2 ON: GPIO-28 will be controlled by the USB-to-UART adapter on the FTDI chip
- POS 2 OFF: GPIO-28 can be controlled by a pin in HSEC connector

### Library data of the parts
C19:A C20:A C21:A C22:A C23:A C24:A C25:A = CMP-0006221-2: as C9 on sheet MCU072E1_Power
C26:A = CMP-0082066-1: CAP, CERM, 10 pF, 3000 V,+/- 5%, C0G/NP0, AEC-Q200 Grade 1, 1812; Manufacturer: Kemet; SizeAreaWB_mm2: 23.1; SizeArea_mm2: 14.4; AEC Qualified: Y; AEC Category: Q200; Value: 10pF; TaMax_C: 125°C; SizeZ_mm: 1.8; AEC Grade: 1; Polarized: N; TaMin_C: -55°C; SizeY_mm: 3.2; Value2: 3000V; U/M: EA; SizeX_mm: 4.5; Cap_Case: 1812
R15:A R16:A = CMP-0026825-5: as R2:A on sheet MCU072E1_Emulator_Hardware
S1:A = CMP-0002230-1: Switch, SPST, 2 Pos, 25mA, 24VDC, SMD; Manufacturer: CTS Electrocomponents; VDC_V: 24V; SwitchFunction: Off-On; PositionCount: 2; CurrentRating_mA: 25A
U5:A U6:A U8:A = CMP-0029375-1: 25 Mbps Dual Channels, 2 / 0, Digital Isolator, 3.3 V / 5 V, -40 to +125 degC, 8-pin SOIC (D), Green (RoHS & no Sb/Br); Manufacturer: Texas Instruments; Datarate(Mbps): 25; Input Noise Filter: Yes; Insulation Rating(VRMS): 2500; Prop Delay(Max)(ns): 42; Rating: Catalog; Supply Voltage(s)(V): 3.3, 5; TTL/CMOS Input Threshold: TTL
U7:A = CMP-0047070-3: Octal Buffer/Driver With 3-State OUtputs, PW0020A (TSSOP-20); Manufacturer: Texas Instruments; Bits(#): 8; F @ Nom Voltage(Max)(Mhz): 100; ICC @ Nom Voltage(Max)(mA): 0.024; Input Type: LVTTL; Rating: Catalog; tpd @ Nom Voltage(Max)(ns): 4.4,3.1,2.8; VCC(Max)(V): 3.6; VCC(Min)(V): 1.65; Voltage(Nom)(V): 1.8,2.5,2.7,3.3; AEC Category: Q200; AEC Qualified: N; CompType: IC; SizeArea_mm2: 43.56; SizeAreaWB_mm2: 73.96; SizeX_mm: 6.6; SizeZ_mm: 1.2

## Sheet MCU072E1_Hardware.SchDoc
size 431 x 279 mm; Date: Not shown in title block; ApprovedBy: Not shown in title block; CheckedBy: Not shown in title block; Author: Not shown in title block; CompanyName: Not shown in title block; DrawnBy: Cody Watkins; Engineer: Not shown in title block; Organization: Not shown in title block; Address1: Not shown in title block; Address2: Not shown in title block; Address3: Not shown in title block; Address4: Not shown in title block; DocumentNumber: 7; Revision: Use project parameter SCH_Rev; SheetNumber: 7; SheetTotal: 7; PageSetup: Record=PageOptions¦CenterHorizontal=True¦CenterVertical=True¦PrintScale=1.00¦XCorrection=1.00¦YCorrection=1.00¦PrintKind=0¦BorderSize=5000000¦LeftOffset=0¦BottomOffset=0¦Orientation=2¦PaperLength=1000¦PaperWidth=1000¦Scale=100¦PaperSource=15¦PrintQuality=600¦MediaType=1¦DitherType=10¦PaperKind=Letter¦PrintScaleMode=1
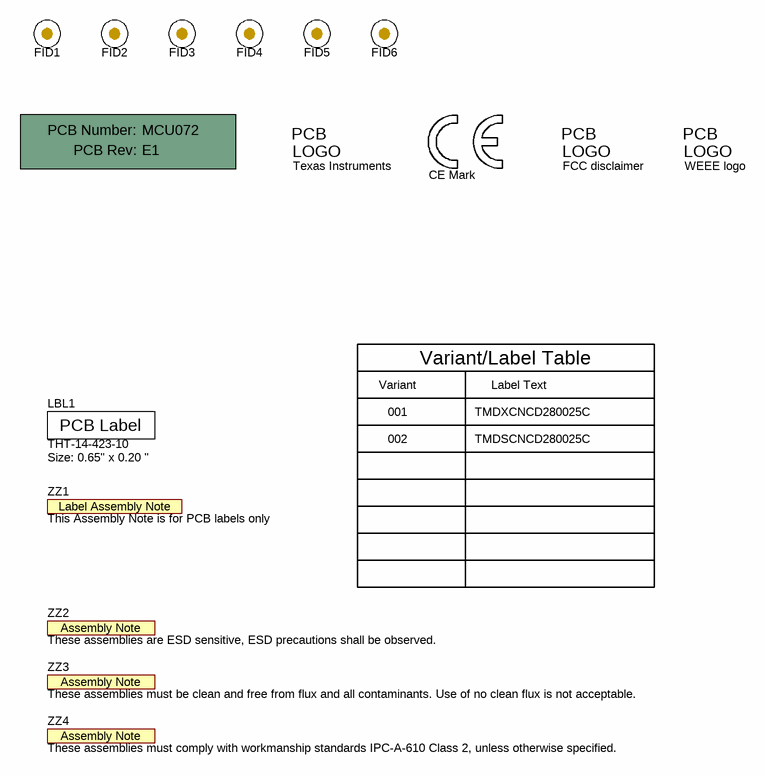
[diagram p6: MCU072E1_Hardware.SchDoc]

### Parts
!PCB1  Printed Circuit Board  (value not drawn)  (mechanical)
FID1  Fiducial  [Fiducial10-20]  (value not drawn)
FID2  Fiducial  [Fiducial10-20]  (value not drawn)
FID3  Fiducial  [Fiducial10-20]  (value not drawn)
FID4  Fiducial  [Fiducial10-20]  (value not drawn)
FID5  Fiducial  [Fiducial10-20]  (value not drawn)
FID6  Fiducial  [Fiducial10-20]  (value not drawn)
LBL1  THT-14-423-10  Note: Size: 0.65" x 0.20 "  [Label_650x200]
Logo1  CE Mark  [CE_Mark_5mm]  (no BOM)
Logo2  Texas Instruments  [TI_Stacked_Overlay_Small]  (no BOM)
Logo3  FCC disclaimer  [FCC_disclaimer]  (no BOM)
Logo4  WEEE logo  [WEEE_Minimum]  (no BOM)
ZZ1  This Assembly Note is for PCB labels only  [AssemblyNoteLabel]  (no BOM)
ZZ2  These assemblies are ESD sensitive, ESD precautions shall be observed.  [AssemblyNote]  (no BOM)
ZZ3  These assemblies must be clean and free from flux and all contaminants. Use of no clean flux is not acceptable.  [AssemblyNote]  (no BOM)
ZZ4  These assemblies must comply with workmanship standards IPC-A-610 Class 2, unless otherwise specified.  [AssemblyNote]  (no BOM)

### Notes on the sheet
- Variant
- Variant/Label Table
- Label Text
- 001
- 002
- TMDXCNCD280025C
- TMDSCNCD280025C

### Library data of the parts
!PCB1 = CMP-0003618-2: Manufacturer: Any; PartNumber: MCU072
FID1-FID6 = CMP-0077181-1: Fiducial mark.  There is nothing to buy or mount.
LBL1 = CMP-0003625-1: Thermal Transfer Printable Labels, 0.650" W x 0.200" H - 10,000 per roll; Manufacturer: Brady; CompType: Label
Logo1 = CMP-0074844-1: SymbolCreator: a0412235
Logo2 = CMP-0074838-1: Texas Instrument Corporate Signature; SymbolCreator: a0412235; Lib Reference: TI_Logo; Library Reference: Logo
Logo3 = CMP-0074847-1: FCC_disclaimer; Library Reference: Logo
Logo4 = CMP-0074769-1
ZZ1 = CMP-0003616-3
ZZ2 = CMP-0077236-1
ZZ3 = CMP-0077237-1
ZZ4 = CMP-0077238-1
